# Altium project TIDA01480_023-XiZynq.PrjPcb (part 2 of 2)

## Sheet TIDA01480_pg4_DscrtRls.SchDoc
size 431 x 279 mm; Date: Not shown in title block; ApprovedBy: Not shown in title block; CheckedBy: Not shown in title block; Author: Not shown in title block; CompanyName: Not shown in title block; Engineer: Not shown in title block; Organization: Not shown in title block; Address1: Not shown in title block; Address2: Not shown in title block; Address3: Not shown in title block; Address4: Not shown in title block; DocumentNumber: 1; Revision: Use project parameter SCH_Rev; SheetNumber: 4; SheetTotal: 7; PageSetup: Record=PageOptions¦CenterHorizontal=True¦CenterVertical=True¦PrintScale=1.00¦XCorrection=1.00¦YCorrection=1.00¦PrintKind=0¦BorderSize=5000000¦LeftOffset=0¦BottomOffset=0¦Orientation=2¦PaperLength=1000¦PaperWidth=1000¦Scale=100¦PaperSource=15¦PrintQuality=600¦MediaType=1¦DitherType=10¦PaperKind=Letter¦PrintScaleMode=1
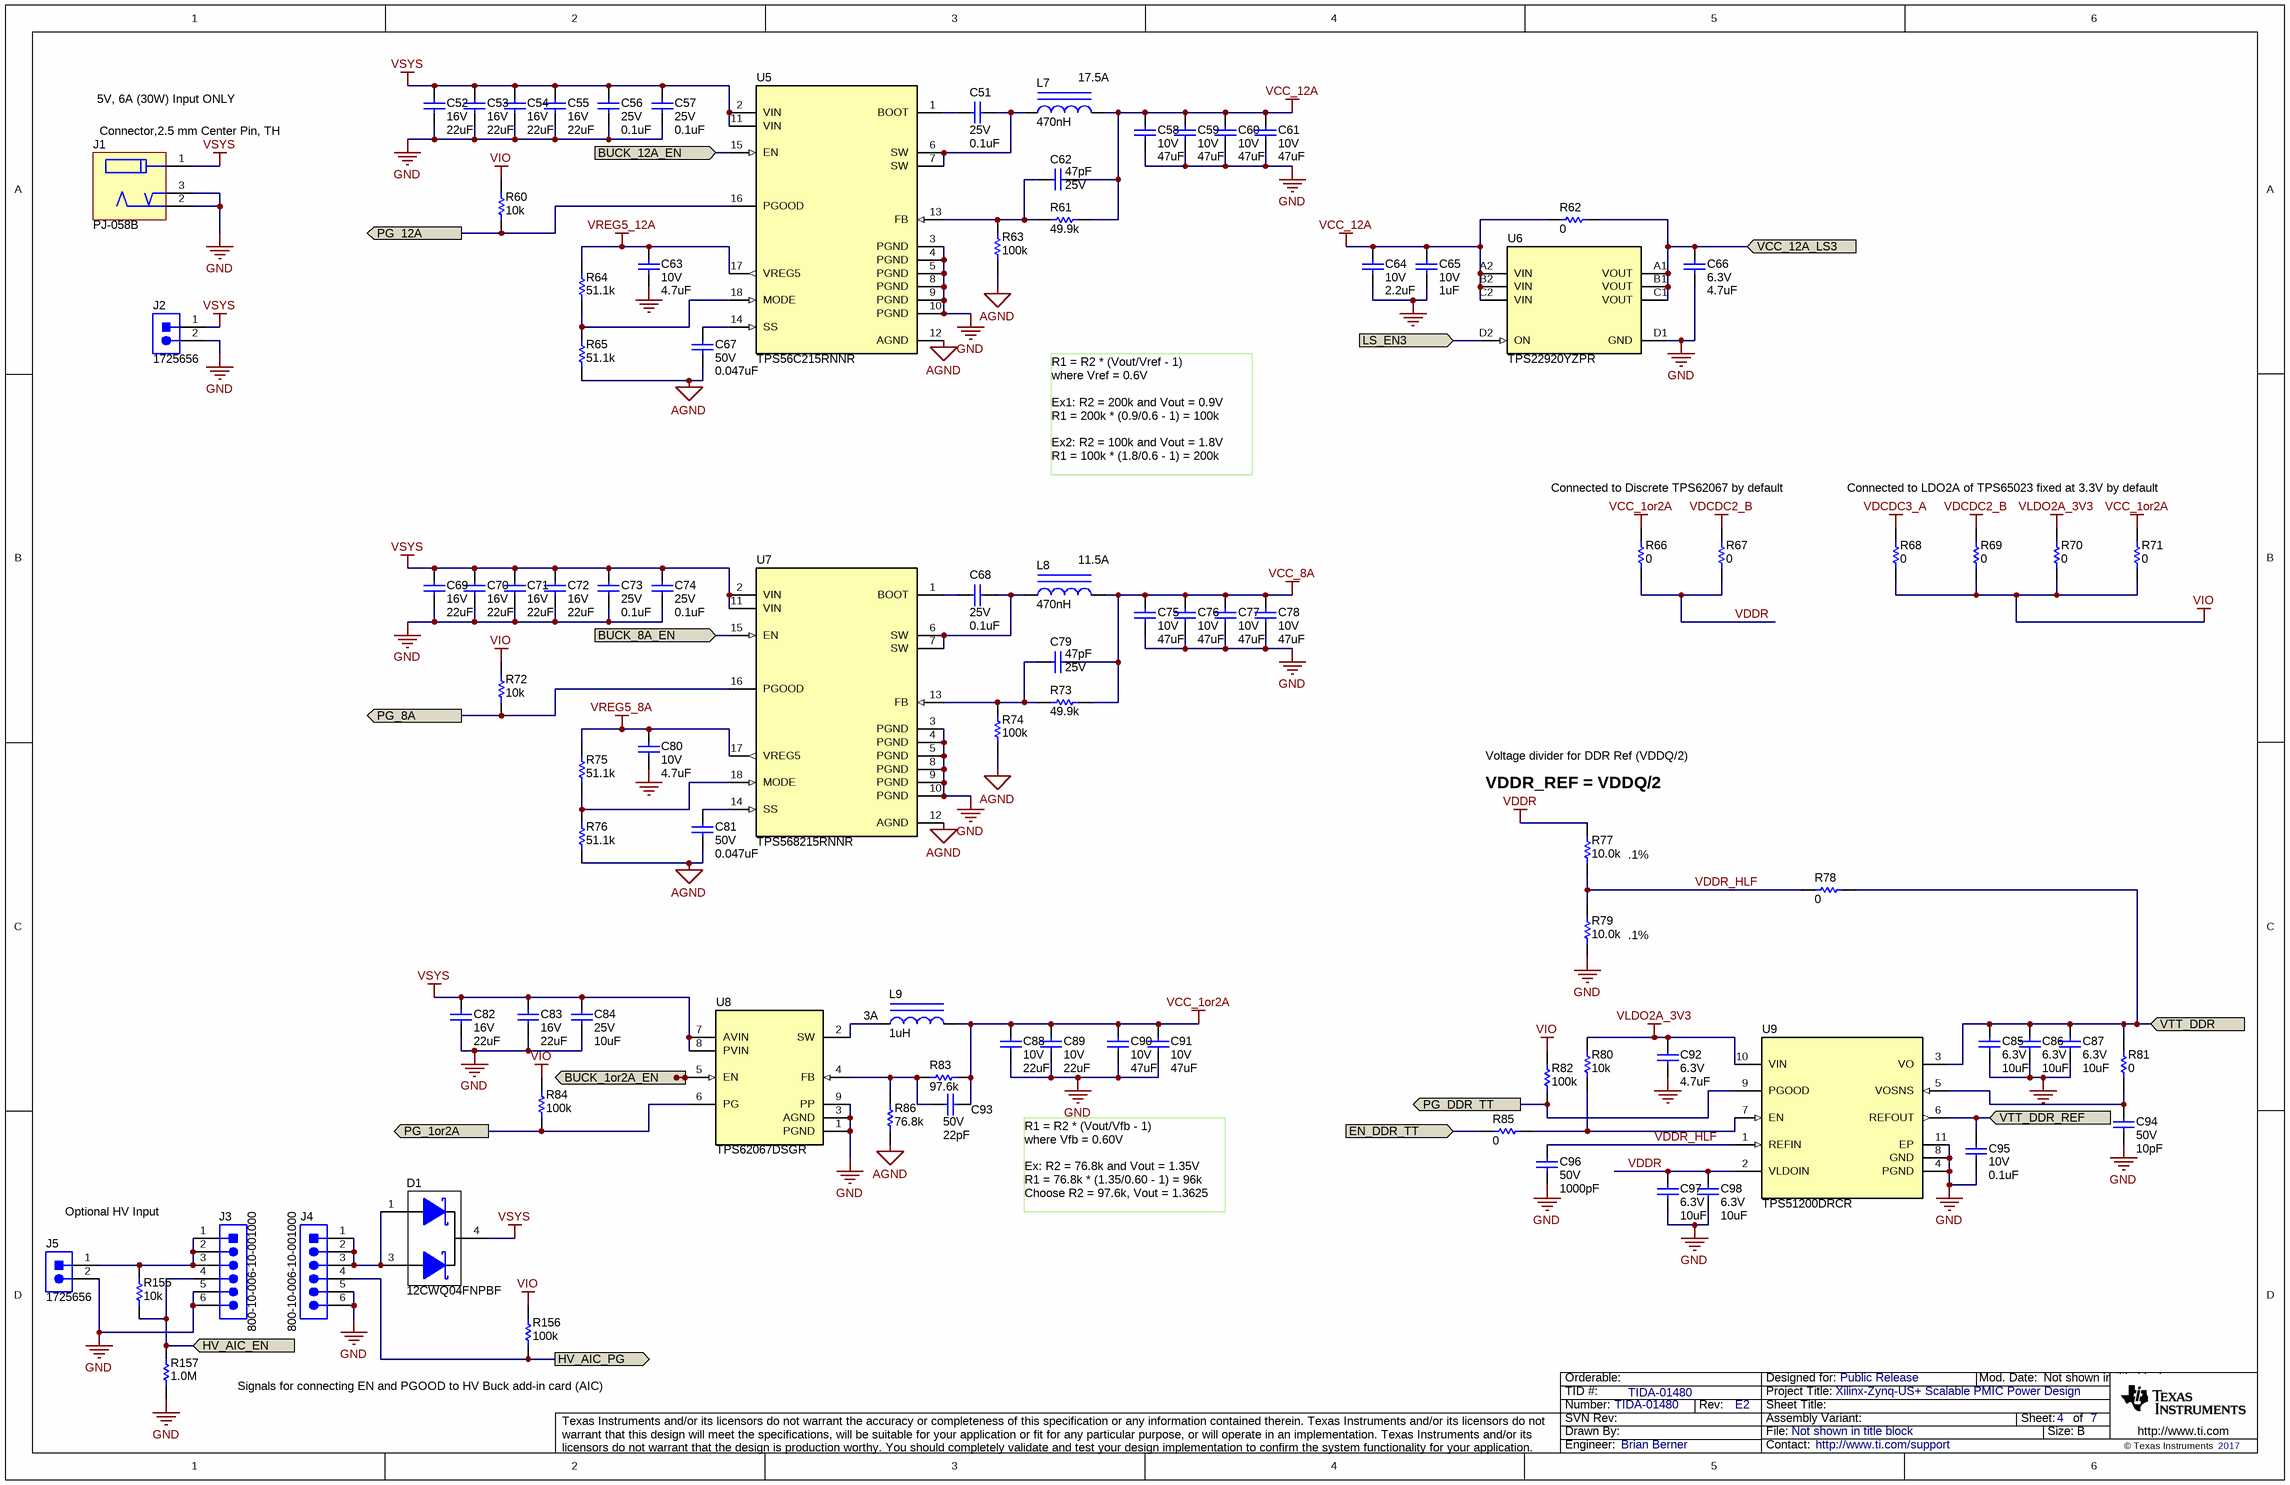
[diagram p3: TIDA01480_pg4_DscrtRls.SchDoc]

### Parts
C51  VDC_V: 25V  ValueDisplayed: 0.1uF  [0402]  (hidden comment: C1005X7R1E104M050BB)
C52  VDC_V: 16V  ValueDisplayed: 22uF  [1210_280]  (hidden comment: C3225X7R1C226K250AC)
C53  VDC_V: 16V  ValueDisplayed: 22uF  [1210_280]  (hidden comment: C3225X7R1C226K250AC)
C54  VDC_V: 16V  ValueDisplayed: 22uF  [1210_280]  (hidden comment: C3225X7R1C226K250AC)
C55  VDC_V: 16V  ValueDisplayed: 22uF  [1210_280]  (hidden comment: C3225X7R1C226K250AC)
C56  VDC_V: 25V  ValueDisplayed: 0.1uF  [0402]  (hidden comment: C1005X7R1E104M050BB)
C57  VDC_V: 25V  ValueDisplayed: 0.1uF  [0402]  (hidden comment: C1005X7R1E104M050BB)
C58  VDC_V: 10V  ValueDisplayed: 47uF  [1210_270]  (hidden comment: GRM32ER71A476KE15L)
C59  VDC_V: 10V  ValueDisplayed: 47uF  [1210_270]  (hidden comment: GRM32ER71A476KE15L)
C60  VDC_V: 10V  ValueDisplayed: 47uF  [1210_270]  (hidden comment: GRM32ER71A476KE15L)
C61  VDC_V: 10V  ValueDisplayed: 47uF  [1210_270]  (hidden comment: GRM32ER71A476KE15L)
C62  VDC_V: 25V  ValueDisplayed: 47pF  [0402]  (hidden comment: GRM1555C1E470JA01D)
C63  VDC_V: 10V  ValueDisplayed: 4.7uF  [0603]  (hidden comment: CGB3B1X5R1A475K055AC)
C64  VDC_V: 10V  ValueDisplayed: 2.2uF  [0603]  (hidden comment: GRM188R71A225KE15D)
C65  VDC_V: 10V  ValueDisplayed: 1uF  [0402]  (hidden comment: GRM155R61A105ME15D)
C66  VDC_V: 6.3V  ValueDisplayed: 4.7uF  [0603]  (hidden comment: JMK107BB7475MA-T)
C67  VDC_V: 50V  ValueDisplayed: 0.047uF  [0402]  (hidden comment: C1005X7R1H473K050BB)
C68  VDC_V: 25V  ValueDisplayed: 0.1uF  [0402]  (hidden comment: C1005X7R1E104M050BB)
C69  VDC_V: 16V  ValueDisplayed: 22uF  [1210_280]  (hidden comment: C3225X7R1C226K250AC)
C70  VDC_V: 16V  ValueDisplayed: 22uF  [1210_280]  (hidden comment: C3225X7R1C226K250AC)
C71  VDC_V: 16V  ValueDisplayed: 22uF  [1210_280]  (hidden comment: C3225X7R1C226K250AC)
C72  VDC_V: 16V  ValueDisplayed: 22uF  [1210_280]  (hidden comment: C3225X7R1C226K250AC)
C73  VDC_V: 25V  ValueDisplayed: 0.1uF  [0402]  (hidden comment: C1005X7R1E104M050BB)
C74  VDC_V: 25V  ValueDisplayed: 0.1uF  [0402]  (hidden comment: C1005X7R1E104M050BB)
C75  VDC_V: 10V  ValueDisplayed: 47uF  [1210_270]  (hidden comment: GRM32ER71A476KE15L)
C76  VDC_V: 10V  ValueDisplayed: 47uF  [1210_270]  (hidden comment: GRM32ER71A476KE15L)
C77  VDC_V: 10V  ValueDisplayed: 47uF  [1210_270]  (hidden comment: GRM32ER71A476KE15L)
C78  VDC_V: 10V  ValueDisplayed: 47uF  [1210_270]  (hidden comment: GRM32ER71A476KE15L)
C79  VDC_V: 25V  ValueDisplayed: 47pF  [0402]  (hidden comment: GRM1555C1E470JA01D)
C80  VDC_V: 10V  ValueDisplayed: 4.7uF  [0603]  (hidden comment: CGB3B1X5R1A475K055AC)
C81  VDC_V: 50V  ValueDisplayed: 0.047uF  [0402]  (hidden comment: C1005X7R1H473K050BB)
C82  VDC_V: 16V  ValueDisplayed: 22uF  [1210_280]  (hidden comment: C3225X7R1C226K250AC)
C83  VDC_V: 16V  ValueDisplayed: 22uF  [1210_280]  (hidden comment: C3225X7R1C226K250AC)
C84  VDC_V: 25V  ValueDisplayed: 10uF  [1206_190]  (hidden comment: C3216X7R1E106M160AE)
C85  VDC_V: 6.3V  ValueDisplayed: 10uF  [0805_HV]  (hidden comment: GRM21BR70J106KE76L)
C86  VDC_V: 6.3V  ValueDisplayed: 10uF  [0805_HV]  (hidden comment: GRM21BR70J106KE76L)
C87  VDC_V: 6.3V  ValueDisplayed: 10uF  [0805_HV]  (hidden comment: GRM21BR70J106KE76L)
C88  VDC_V: 10V  ValueDisplayed: 22uF  [0805_HV]  (hidden comment: C2012X7S1A226M125AC)
C89  VDC_V: 10V  ValueDisplayed: 22uF  [0805_HV]  (hidden comment: C2012X7S1A226M125AC)
C90  VDC_V: 10V  ValueDisplayed: 47uF  [1210_270]  (hidden comment: GRM32ER71A476KE15L)
C91  VDC_V: 10V  ValueDisplayed: 47uF  [1210_270]  (hidden comment: GRM32ER71A476KE15L)
C92  VDC_V: 6.3V  ValueDisplayed: 4.7uF  [0805_HV]  (hidden comment: GRM21BR60J475KA11L)
C93  VDC_V: 50V  ValueDisplayed: 22pF  [0402]  (hidden comment: GCM1555C1H220JA16D)
C94  VDC_V: 50V  ValueDisplayed: 10pF  [0402]  (hidden comment: GRM1555C1H100JA01D)
C95  VDC_V: 10V  ValueDisplayed: 0.1uF  [0402]  (hidden comment: GRM155R71A104KA01D)
C96  VDC_V: 50V  ValueDisplayed: 1000pF  [0402]  (hidden comment: C1005X7R1H102M050BE)
C97  VDC_V: 6.3V  ValueDisplayed: 10uF  [0805_HV]  (hidden comment: GRM21BR70J106KE76L)
C98  VDC_V: 6.3V  ValueDisplayed: 10uF  [0805_HV]  (hidden comment: GRM21BR70J106KE76L)
D1  12CWQ04FNPBF  [DPAK]
J1  PJ-058B  PackageReference: Connector,2.5 mm Center Pin, TH  [CUI_PJ-058B]
J2  1725656  [CONN_1725656]
J3  800-10-006-10-001000  [Mill-Max_800-10-006-10-001000]
J4  800-10-006-10-001000  [Mill-Max_800-10-006-10-001000]
J5  1725656  [CONN_1725656]
L7  Imax_A: 17.5A  ValueDisplayed: 470nH  [IHLP-2525CZ]  (hidden comment: IHLP2525CZERR47M01)
L8  Imax_A: 11.5A  ValueDisplayed: 470nH  [IHLP-2020BZ]  (hidden comment: IHLP2020BZERR47M01)
L9  Imax_A: 3A  ValueDisplayed: 1uH  [IHLP-1212AB]  (hidden comment: IHLP1212ABER1R0M11)
R60  ValueDisplayed: 10k  [0402]  (hidden comment: CRCW040210K0JNED)
R61  ValueDisplayed: 49.9k  [0402]  (hidden comment: ERJ-2RKF4992X)
R62  ValueDisplayed: 0  [1206]  (hidden comment: CRCW12060000Z0EA)
R63  ValueDisplayed: 100k  [0402]  (hidden comment: RG1005P-104-B-T5)
R64  ValueDisplayed: 51.1k  [0402]  (hidden comment: CRCW040251K1FKED)
R65  ValueDisplayed: 51.1k  [0402]  (hidden comment: CRCW040251K1FKED)
R66  ValueDisplayed: 0  [1206]  (hidden comment: CRCW12060000Z0EA)
R67  ValueDisplayed: 0  [1206]  (hidden comment: CRCW12060000Z0EA)
R68  ValueDisplayed: 0  [1206]  (hidden comment: CRCW12060000Z0EA)
R69  ValueDisplayed: 0  [1206]  (hidden comment: CRCW12060000Z0EA)
R70  ValueDisplayed: 0  [1206]  (hidden comment: CRCW12060000Z0EA)
R71  ValueDisplayed: 0  [1206]  (hidden comment: CRCW12060000Z0EA)
R72  ValueDisplayed: 10k  [0402]  (hidden comment: CRCW040210K0JNED)
R73  ValueDisplayed: 49.9k  [0402]  (hidden comment: ERJ-2RKF4992X)
R74  ValueDisplayed: 100k  [0402]  (hidden comment: RG1005P-104-B-T5)
R75  ValueDisplayed: 51.1k  [0402]  (hidden comment: CRCW040251K1FKED)
R76  ValueDisplayed: 51.1k  [0402]  (hidden comment: CRCW040251K1FKED)
R77  Value1: .1%  ValueDisplayed: 10.0k  [0402]  (hidden comment: RT0402BRD0710KL)
R78  ValueDisplayed: 0  [1206]  (hidden comment: CRCW12060000Z0EA)
R79  Value1: .1%  ValueDisplayed: 10.0k  [0402]  (hidden comment: RT0402BRD0710KL)
R80  ValueDisplayed: 10k  [0402]  (hidden comment: CRCW040210K0JNED)
R81  ValueDisplayed: 0  [0402]  (hidden comment: CRCW04020000Z0ED)
R82  ValueDisplayed: 100k  [0402]  (hidden comment: CRCW0402100KJNED)
R83  ValueDisplayed: 97.6k  [0402]  (hidden comment: ERJ-2RKF9762X)
R84  ValueDisplayed: 100k  [0402]  (hidden comment: CRCW0402100KJNED)
R85  ValueDisplayed: 0  [0402]  (hidden comment: CRCW04020000Z0ED)
R86  ValueDisplayed: 76.8k  [0402]  (hidden comment: ERA-2AEB7682X)
R155  ValueDisplayed: 10k  [0402]  (hidden comment: CRCW040210K0JNED)
R156  ValueDisplayed: 100k  [0402]  (hidden comment: CRCW0402100KJNED)
R157  ValueDisplayed: 1.0M  [0402]  (hidden comment: CRCW04021M00JNED)
U5  TPS56C215RNNR  [RNN0018A]
U6  TPS22920YZPR  [YZP0008ADCD]
U7  TPS568215RNNR  [RNN0018A]
U8  TPS62067DSGR  [DSG0008A]
U9  TPS51200DRCR  [DRC0010J]

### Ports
BUCK_1or2A_EN (in), BUCK_8A_EN (in), BUCK_12A_EN (in), EN_DDR_TT (in), HV_AIC_EN (in), HV_AIC_PG (out), LS_EN3 (in), PG_1or2A (out), PG_8A (out), PG_12A (out), PG_DDR_TT (out), VCC_12A_LS3, VTT_DDR, VTT_DDR_REF

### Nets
AGND: C67.2 C81.2 R63.1 R65.1 R74.1 R76.1 R86.1 U5.12(AGND) U7.12(AGND)
GND: C52.2 C53.2 C54.2 C55.2 C56.2 C57.2 C58.2 C59.2 C60.2 C61.2 C63.2 C64.2 C65.2 C66.2 C69.2 C70.2 C71.2 C72.2 C73.2 C74.2 C75.2 C76.2 C77.2 C78.2 C80.2 C82.2 C83.2 C84.2 C85.2 C86.2 C87.2 C88.2 C89.2 C90.2 C91.2 C92.2 C94.2 C95.2 C96.2 C97.2 C98.2 J1.2 J1.3 J2.2 J3.5 J3.6 J4.5 J4.6 J5.2 R79.1 R157.1 U5.3(PGND) U5.4(PGND) U5.5(PGND) U5.8(PGND) U5.9(PGND) U5.10(PGND) U6.D1(GND) U7.3(PGND) U7.4(PGND) U7.5(PGND) U7.8(PGND) U7.9(PGND) U7.10(PGND) U8.1(PGND) U8.3(AGND) U8.9(PP) U9.4(PGND) U9.8(GND) U9.11(EP)
VCC_1or2A: C88.1 C89.1 C90.1 C91.1 C93.1 L9.2 R66.2 R71.2 R83.1
VCC_8A: C75.1 C76.1 C77.1 C78.1 C79.1 L8.2 R73.2
VCC_12A: C58.1 C59.1 C60.1 C61.1 C62.1 C64.1 C65.1 L7.2 R61.2 R62.1 U6.A2(VIN) U6.B2(VIN) U6.C2(VIN)
VDCDC2_B: R67.2 R69.2
VDCDC3_A: R68.2
VDDR: C97.1 C98.1 R66.1 R67.1 R77.2 U9.2(VLDOIN)
VIO: R60.1 R68.1 R69.1 R70.1 R71.1 R72.1 R82.1 R84.1 R156.1
VLDO2A_3V3: C92.1 R70.2 R80.1 U9.10(VIN)
VREG5_8A: C80.1 R75.2 U7.17(VREG5)
VREG5_12A: C63.1 R64.2 U5.17(VREG5)
VSYS: C52.1 C53.1 C54.1 C55.1 C56.1 C57.1 C69.1 C70.1 C71.1 C72.1 C73.1 C74.1 C82.1 C83.1 C84.1 D1.4(K) J1.1 J2.1 U5.2(VIN) U5.11(VIN) U7.2(VIN) U7.11(VIN) U8.7(AVIN) U8.8(PVIN)
BUCK_1or2A_EN: U8.5(EN) ; port BUCK_1or2A_EN
BUCK_8A_EN: U7.15(EN) ; port BUCK_8A_EN
BUCK_12A_EN: U5.15(EN) ; port BUCK_12A_EN
DDR_Strt_PG: R84.2 U8.6(PG) ; port PG_1or2A
DDR_TT_PG: R82.2 U9.9(PGOOD) ; port PG_DDR_TT
EN_DDR_TERM: R85.2 ; port EN_DDR_TT
EN_PRE_BUCK: J3.4 R155.2 R157.2 ; port HV_AIC_EN
EN_SEQ_LS3: U6.D2(ON) ; port LS_EN3
HiCurrent_PG: R60.2 U5.16(PGOOD) ; port PG_12A
HV_AIC_PG: J4.4 R156.2 ; port HV_AIC_PG
MidCurrent_PG: R72.2 U7.16(PGOOD) ; port PG_8A
VCC_12A_LS3: C66.1 R62.2 U6.A1(VOUT) U6.B1(VOUT) U6.C1(VOUT) ; port VCC_12A_LS3
VDDR_HLF: C96.1 R77.1 R78.1 R79.2 U9.1(REFIN)
VREFCA_DDR: C95.1 U9.6(REFOUT) ; port VTT_DDR_REF
VTT: C85.1 C86.1 C87.1 R78.2 R81.2 U9.3(VO) ; port VTT_DDR
NetC51_1: C51.1 U5.1(BOOT)
NetC51_2: C51.2 L7.1 U5.6(SW) U5.7(SW)
NetC62_2: C62.2 R61.1 R63.2 U5.13(FB)
NetC67_1: C67.1 U5.14(SS)
NetC68_1: C68.1 U7.1(BOOT)
NetC68_2: C68.2 L8.1 U7.6(SW) U7.7(SW)
NetC79_2: C79.2 R73.1 R74.2 U7.13(FB)
NetC81_1: C81.1 U7.14(SS)
NetC93_2: C93.2 R83.2 R86.2 U8.4(FB)
NetC94_1: C94.1 R81.1 U9.5(VOSNS)
NetD1_1: D1.1(A) D1.3(A) J4.1 J4.2 J4.3
NetJ3_1: J3.1 J3.2 J3.3 J5.1 R155.1
NetL9_1: L9.1 U8.2(SW)
NetR64_1: R64.1 R65.2 U5.18(MODE)
NetR75_1: R75.1 R76.2 U7.18(MODE)
NetR80_2: R80.2 R85.1 U9.7(EN)

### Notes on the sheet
- 5V, 6A (30W) Input ONLY
- R1 = R2 * (Vout/Vref - 1)
  where Vref = 0.6V
  Ex1: R2 = 200k and Vout = 0.9V
  R1 = 200k * (0.9/0.6 - 1) = 100k
  Ex2: R2 = 100k and Vout = 1.8V
  R1 = 100k * (1.8/0.6 - 1) = 200k
- Connected to Discrete TPS62067 by default
- Connected to LDO2A of TPS65023 fixed at 3.3V by default
- Voltage divider for DDR Ref (VDDQ/2)
- (near R77) VDDR_REF = VDDQ/2
- Optional HV Input
- R1 = R2 * (Vout/Vfb - 1)
  where Vfb = 0.60V
  Ex: R2 = 76.8k and Vout = 1.35V
  R1 = 76.8k * (1.35/0.60 - 1) = 96k
  Choose R2 = 97.6k, Vout = 1.3625
- (near R156) Signals for connecting EN and PGOOD to HV Buck add-in card (AIC)

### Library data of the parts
C51 C56 C57 C68 C73 C74 = CMP-0006295-2: CAP, CERM, 0.1 uF, 25 V, +/- 20%, X7R, 0402; Manufacturer: TDK; TaMin_C: -55°C; Polarized: N; SizeAreaWB_mm2: 3; Value1: Unknown; U/M: EA; Value: 0.1uF; TaMax_C: 125°C; SizeZ_mm: 0.6; SizeX_mm: 1; SizeY_mm: 0.5; Cap_F: 100nF; AEC Category: Q200
C52-C55 C69-C72 C82 C83 = CMP-0009116-1: CAP, CERM, 22 uF, 16 V, +/- 10%, X7R, 1210; Manufacturer: TDK; TaMin_C: -55°C; ESR_ohm: 2.582m; Polarized: N; SizeAreaWB_mm2: 14.7; Value1: 0.002582 ohm; U/M: EA; Value: 22uF; TaMax_C: 125°C; SizeZ_mm: 2.8; SizeX_mm: 3.2; SizeY_mm: 2.5; SizeArea_mm2: 8; Cap_F: 22µF; IRMS_A: 4.57562A; AEC Category: Q200
C58-C61 C75-C78 C90 C91 = CMP-0009220-2: CAP, CERM, 47 uF, 10 V, +/- 10%, X7R, 1210; Manufacturer: MuRata; TaMin_C: -55°C; Polarized: N; SizeAreaWB_mm2: 14.7; Value1: Unknown; U/M: EA; Value: 47uF; TaMax_C: 125°C; SizeZ_mm: 2.7; SizeX_mm: 3.2; SizeY_mm: 2.5; Cap_Case: 1210; SizeArea_mm2: 8; Cap_F: 47µF; AEC Category: Q200
C62 C79 = CMP-0006388-2: CAP, CERM, 47 pF, 25 V, +/- 5%, C0G/NP0, 0402; Manufacturer: MuRata; TaMin_C: -55°C; Polarized: N; SizeAreaWB_mm2: 3; Value1: Unknown; U/M: EA; Value: 47pF; TaMax_C: 125°C; SizeZ_mm: 0.6; SizeX_mm: 1; SizeY_mm: 0.5; AEC Category: Q200
C63 C80 = CMP-0007105-5: CAP, CERM, 4.7 uF, 10 V, +/- 10%, X5R, 0603; Manufacturer: TDK; TaMin_C: -55°C; Polarized: N; SizeAreaWB_mm2: 4.68; Value1: Unknown; U/M: EA; Value: 4.7uF; TaMax_C: 85°C; SizeZ_mm: 1; SizeX_mm: 1.6; SizeY_mm: 0.8; SizeArea_mm2: 1.28; Cap_F: 4.7µF; AEC Category: Q200
C64 = CMP-0007370-3: CAP, CERM, 2.2 uF, 10 V, +/- 10%, X7R, 0603; Manufacturer: MuRata; TaMin_C: -55°C; ESR_ohm: 9m; Polarized: N; SizeAreaWB_mm2: 4.68; Value1: 0.009 ohm; U/M: EA; Value: 2.2uF; TaMax_C: 125°C; SizeZ_mm: 1; SizeX_mm: 1.6; SizeY_mm: 0.8; SizeArea_mm2: 1.28; Cap_F: 2.2µF; AEC Category: Q200
C65 = CMP-0064927-2: CAP, CERM, 1 uF, 10 V,+/- 20%, X5R, 0402; Manufacturer: MuRata; TaMin_C: -55°C; Polarized: N; SizeAreaWB_mm2: 3; Value1: Unknown; U/M: EA; Value: 1uF; TaMax_C: 85°C; SizeZ_mm: 0.6; SizeX_mm: 1; SizeY_mm: 0.5; CompType: Capacitor; Cap_F: 1µF; AEC Category: Q200
C66 = CMP-0007503-3: CAP, CERM, 4.7 uF, 6.3 V, +/- 10%, X7R, 0603; Manufacturer: Taiyo Yuden; TaMin_C: -55°C; Polarized: N; SizeAreaWB_mm2: 4.68; Value1: Unknown; U/M: EA; Value: 4.7uF; TaMax_C: 125°C; SizeZ_mm: 1; SizeX_mm: 1.6; SizeY_mm: 0.8; SizeArea_mm2: 1.28; Cap_F: 4.7µF; AEC Category: Q200
C67 C81 = CMP-0006298-2: CAP, CERM, 0.047 uF, 50 V, +/- 10%, X7R, 0402; Manufacturer: TDK; TaMin_C: -55°C; ESR_ohm: 0.06407; Polarized: N; SizeAreaWB_mm2: 3; Value1: 0.06407 ohm; U/M: EA; SizeZ_mm: 0.6; SizeX_mm: 1; SizeY_mm: 0.5; Cap_F: 47nF; IRMS_A: 6.46122dA; AEC Category: Q200; TaMax_C: 125°C
C84 = CMP-0008692-2: CAP, CERM, 10 uF, 25 V, +/- 20%, X7R, 1206_190; Manufacturer: TDK; TaMin_C: -55°C; Polarized: N; SizeAreaWB_mm2: 10.92; Value1: Unknown; U/M: EA; Value: 10uF; TaMax_C: 125°C; SizeZ_mm: 1.9; SizeX_mm: 3.2; SizeY_mm: 1.6; Cap_Case: 1206; SizeArea_mm2: 5.12; CompType: Capacitor; Cap_F: 10µF; AEC Category: Q200
C85-C87 C97 C98 = CMP-0008311-2: CAP, CERM, 10 uF, 6.3 V, +/- 10%, X7R, 0805; Manufacturer: MuRata; TaMin_C: -55°C; Polarized: N; SizeAreaWB_mm2: 6.75; Value1: Unknown; U/M: EA; Value: 10uF; TaMax_C: 125°C; SizeZ_mm: 1.45; SizeX_mm: 2; SizeY_mm: 1.25; Cap_Case: 0805; SizeArea_mm2: 2.5; Cap_F: 10µF; AEC Category: Q200
C88 C89 = CMP-0007890-2: CAP, CERM, 22 uF, 10 V, +/- 20%, X7S, 0805; Manufacturer: TDK; TaMin_C: -55°C; ESR_ohm: 2.05m; Polarized: N; SizeAreaWB_mm2: 6.75; Value1: 0.00205 ohm; U/M: EA; Value: 22uF; TaMax_C: 125°C; SizeZ_mm: 1.45; SizeX_mm: 2; SizeY_mm: 1.25; Cap_Case: 0805; SizeArea_mm2: 2.5; Cap_F: 22µF; IRMS_A: 4.55587A; AEC Category: Q200
C92 = CMP-0008283-2: CAP, CERM, 4.7 uF, 6.3 V, +/- 10%, X5R, 0805; Manufacturer: MuRata; TaMin_C: -55°C; Polarized: N; SizeAreaWB_mm2: 6.75; Value1: Unknown; U/M: EA; Value: 4.7uF; TaMax_C: 85°C; SizeZ_mm: 1.45; SizeX_mm: 2; SizeY_mm: 1.25; Cap_Case: 0805; SizeArea_mm2: 2.5; Cap_F: 4.7µF; AEC Category: Q200
C93 = CMP-0006348-2: CAP, CERM, 22 pF, 50 V, +/- 5%, C0G/NP0, AEC-Q200 Grade 1, 0402; Manufacturer: MuRata; TaMin_C: -55°C; Polarized: N; SizeAreaWB_mm2: 3; Value1: Unknown; U/M: EA; Value: 22pF; TaMax_C: 125°C; SizeZ_mm: 0.6; SizeX_mm: 1; SizeY_mm: 0.5; AEC Qualified: Y; AEC Category: Q200
C94 = CMP-0006408-2: CAP, CERM, 10 pF, 50 V, +/- 5%, C0G/NP0, 0402; Manufacturer: MuRata; TaMin_C: -55°C; Polarized: N; SizeAreaWB_mm2: 3; Value1: Unknown; U/M: EA; Value: 10pF; TaMax_C: 125°C; SizeZ_mm: 0.6; SizeX_mm: 1; SizeY_mm: 0.5; AEC Category: Q200
C95 = CMP-0006629-2: CAP, CERM, 0.1 uF, 10 V, +/- 10%, X7R, 0402; Manufacturer: MuRata; TaMin_C: -55°C; Polarized: N; SizeAreaWB_mm2: 3; Value1: Unknown; U/M: EA; Value: 0.1uF; TaMax_C: 125°C; SizeZ_mm: 0.6; SizeX_mm: 1; SizeY_mm: 0.5; Cap_F: 100nF; AEC Category: Q200
C96 = CMP-0006296-2: CAP, CERM, 1000 pF, 50 V, +/- 20%, X7R, 0402; Manufacturer: TDK; TaMin_C: -55°C; Polarized: N; SizeAreaWB_mm2: 3; Value1: Unknown; U/M: EA; Value: 1000pF; TaMax_C: 125°C; SizeZ_mm: 0.6; SizeX_mm: 1; SizeY_mm: 0.5; Cap_F: 1nF; AEC Category: Q200
D1 = CMP-0028356-1: Diode, Schottky, 40 V, 12 A, DPAK; Manufacturer: Vishay-Semiconductor; Io_A: 12A; Green_Lifecycle: Not Set; SizeAreaWB_mm2: 101.7114; Vr_V: 40V; Green_REACh: Incomplete; TJmax_C: 150°C; U/M: EA; Value: 40V; SizeZ_mm: 2.29; SizeX_mm: 9.91; SizeY_mm: 6.54; Vf_V: 6.8dV; Value2: 0.68V; SizeArea_mm2: 64.8114; AEC Category: Q101; RJC_CperW: 1.5
J1 = CMP-0075310-1: Connector, DC Jack 2.5 mm Center Pin, TH; Manufacturer: CUI Inc.; CNHeader: False; Current_A: 2.5A; Gender: Female; Voltage_V: 24V; CompType: Power Jack; ContactFinish: Nickel; Cert_UL: Y
J2 J5 = CMP-0055479-1: Terminal Block, 100mil, 2x1, 6A, 63V, TH; Manufacturer: Phoenix Contact; CNHeader: FALSE; Green_Lifecycle: Not Set; Green_REACh: Incomplete; CT: TRUE
J3 J4 = CMP-0055084-1: Header, 100mil, 6x1, TH; Manufacturer: Mill-Max; CT: FALSE; CNHeader: TRUE
L7 = CMP-0063396-1: Inductor, Shielded Drum Core, Powdered Iron, 470 nH, 17.5 A, 0.004 ohm, SMD; Manufacturer: Vishay-Dale; Isat: 26A @ 20% inductance drop; Irms: 17.5A @ 40C rise; Green_Lifecycle: Active; SizeAreaWB_mm2: 75.0442; DCR_ohm: 4m; Green_REACh: Passed; Value: 470nH; SizeZ_mm: 3; SizeX_mm: 6.86; SizeY_mm: 6.47; SizeArea_mm2: 44.3842; AEC Category: Q200
L8 = CMP-0063307-1: Inductor, Shielded Drum Core, Powdered Iron, 470 nH, 11.5 A, 0.0081 ohm, SMD; Manufacturer: Vishay-Dale; Isat: 21A @ 20% inductance drop; Irms: 11.5A @ 40C rise; Green_Lifecycle: Active; SizeAreaWB_mm2: 53.7782; DCR_ohm: 8.1m; Green_REACh: Passed; Value: 470nH; SizeZ_mm: 2; SizeX_mm: 5.49; SizeY_mm: 5.18; SizeArea_mm2: 28.4382; AEC Category: Q200
L9 = CMP-0063238-1: Inductor, Shielded Drum Core, Powdered Iron, 1 uH, 3 A, 0.038 ohm, SMD; Manufacturer: Vishay-Dale; Isat: 4.5A @ 20% inductance drop; Irms: 3A @ 40C rise; Green_Lifecycle: Active; SizeAreaWB_mm2: 19.32; DCR_ohm: 0.038; Green_REACh: Passed; Value: 1uH; SizeZ_mm: 1.2; SizeX_mm: 3.6; SizeY_mm: 3.2; SizeArea_mm2: 11.52; Ind_H: 1µH; AEC Category: Q200
R60 R72 R80 R155 = CMP-0026825-4: RES, 10 k, 5%, 0.063 W, 0402; Manufacturer: Vishay-Dale; Power_W: 63mW; TempCo: 200 ppm/C; Value_Code: 10k0; U/M: EA; Value: 10k; EIA_Code: E24; SizeX_mm: 1; SizeY_mm: 0.5; SizeZ_mm: 0.6; Value2: 0.063W; VDC_V: 50V; AEC Category: Q200
R61 R73 = CMP-0026702-1: RES, 49.9 k, 1%, 0.1 W, AEC-Q200 Grade 0, 0402; Manufacturer: Panasonic; Power_W: 100mW; TempCo: 100 ppm/C; Value_Code: 49k9; U/M: EA; Value: 49.9k; EIA_Code: E96; SizeX_mm: 1; SizeY_mm: 0.5; SizeZ_mm: 0.6; Value2: 0.1W; AEC Qualified: Y; VDC_V: 50V; AEC Grade: 0; AEC Category: Q200
R62 R66-R71 R78 = CMP-0018573-2: RES, 0, 5%, 0.25 W, 1206; Manufacturer: Vishay-Dale; Power_W: 250mW; TempCo: 200 ppm/C; Value_Code: 0000; U/M: EA; Value: 0; EIA_Code: E24; SizeX_mm: 3.2; SizeY_mm: 1.6; SizeZ_mm: 1.35; Value2: 0.25W; SizeArea_mm2: 5.12; VDC_V: 200V; AEC Category: Q200
R63 R74 = CMP-0026815-1: RES, 100 k, 0.1%, 0.063 W, 0402; Manufacturer: Susumu Co Ltd; Power_W: 63mW; TempCo: 25 ppm/C; U/M: EA; Value: 100k; EIA_Code: E192; SizeX_mm: 1; SizeY_mm: 0.5; SizeZ_mm: 0.6; Value2: 0.063W; AEC Category: Q200
R64 R65 R75 R76 = CMP-0026437-1: RES, 51.1 k, 1%, 0.063 W, 0402; Manufacturer: Vishay-Dale; Power_W: 63mW; TempCo: 100 ppm/C; Value_Code: 51k1; U/M: EA; Value: 51.1k; EIA_Code: E96; SizeX_mm: 1; SizeY_mm: 0.5; SizeZ_mm: 0.6; Value2: 0.063W; VDC_V: 50V; AEC Category: Q200
R77 R79 = CMP-0065360-1: RES, 10.0 k, .1%, .0625 W, 0402; Manufacturer: Yageo America; Power_W: 62.5mW; TempCo: 25 ppm/C; Value_Code: 10k0; U/M: EA; Value: 10.0k; EIA_Code: E192; Tolerance_%: 0.1%; Res_ohm: 10k; SizeX_mm: 1.0; SizeY_mm: 0.5; SizeZ_mm: 0.6; Value2: .0625W; CompType: Resistor; VDC_V: 50V; AEC Category: Q200
R81 R85 = CMP-0026822-2: RES, 0, 5%, 0.063 W, 0402; Manufacturer: Vishay-Dale; Power_W: 63mW; TempCo: 200 ppm/C; Value_Code: 0000; U/M: EA; Value: 0; EIA_Code: E24; SizeX_mm: 1; SizeY_mm: 0.5; SizeZ_mm: 0.6; Value2: 0.063W; VDC_V: 50V; AEC Category: Q200
R82 R84 R156 = CMP-0026823-2: RES, 100 k, 5%, 0.063 W, 0402; Manufacturer: Vishay-Dale; Power_W: 63mW; TempCo: 200 ppm/C; U/M: EA; Value: 100k; EIA_Code: E24; SizeX_mm: 1; SizeY_mm: 0.5; SizeZ_mm: 0.6; Value2: 0.063W; VDC_V: 50V; AEC Category: Q200
R83 = CMP-0026712-1: RES, 97.6 k, 1%, 0.1 W, AEC-Q200 Grade 0, 0402; Manufacturer: Panasonic; Power_W: 100mW; TempCo: 100 ppm/C; Value_Code: 97k6; U/M: EA; Value: 97.6k; EIA_Code: E96; SizeX_mm: 1; SizeY_mm: 0.5; SizeZ_mm: 0.6; Value2: 0.1W; AEC Qualified: Y; VDC_V: 50V; AEC Grade: 0; AEC Category: Q200
R86 = CMP-0026787-1: RES, 76.8 k, 0.1%, 0.063 W, AEC-Q200 Grade 0, 0402; Manufacturer: Panasonic; Power_W: 63mW; TempCo: 25 ppm/C; Value_Code: 76k8; U/M: EA; Value: 76.8k; EIA_Code: E192; SizeX_mm: 1; SizeY_mm: 0.5; SizeZ_mm: 0.6; Value2: 0.063W; AEC Qualified: Y; VDC_V: 50V; AEC Grade: 0; AEC Category: Q200
R157 = CMP-0026859-1: RES, 1.0 M, 5%, 0.063 W, 0402; Manufacturer: Vishay-Dale; Power_W: 63mW; TempCo: 200 ppm/C; Value_Code: 1M00; U/M: EA; Value: 1.0Meg; EIA_Code: E24; Res_ohm: 1M; SizeX_mm: 1; SizeY_mm: 0.5; SizeZ_mm: 0.6; Value2: 0.063W; VDC_V: 50V; AEC Category: Q200
U5 = CMP-0074013-1: 4.5V to 17V Input, DCAP3 Mode, 12A Synchronous Step-Down SWIFT(TM) Converter, RNN0018A (VQFN-HR-18); Alternate PartNumber: TPS56C215RNNT; Alternate Manufacturer: Texas Instruments; SizeAreaWB_mm2: 20.25; U/M: EA; SizeZ_mm: 1.0; SizeX_mm: 3.5; SizeArea_mm2: 12.25; CompType: IC
U6 = CMP-0066647-2: 3.6V, 4A, 5.3mΩ Load Switch with Quick Output Discharge, YZP0008ADCD (DSBGA-8); Alternate PartNumber: TPS22920YZPT; Alternate Manufacturer: Texas Instruments; Green_Lifecycle: Active; SizeAreaWB_mm2: 7.3125; Green_REACh: Passed; U/M: EA; SizeZ_mm: 0.5; SizeX_mm: 1.25; SizeY_mm: 2.25; SizeArea_mm2: 2.8125; CompType: IC
U7 = CMP-0074010-1: 4.5V to 17V Input, DCAP3 Mode, 8A Synchronous SWIFT(TM) Step-Down Converter, RNN0018A (VQFN-HR-18); Alternate PartNumber: TPS568215RNNT; Alternate Manufacturer: Texas Instruments; SizeAreaWB_mm2: 20.25; U/M: EA; SizeZ_mm: 1.0; SizeX_mm: 3.5; SizeArea_mm2: 12.25; CompType: IC
U8 = CMP-0037738-2: Buck Step Down Regulator with 2.9 to 6 V Input and 0.8 to 6 V Output, -40 to 85 degC, 8-Pin WSON (DSG), Green (RoHS & no Sb/Br); Manufacturer: Texas Instruments; Vin(Min)(V): 2.9; Switch Current Limit(Typ)(A): 2.75; Vin(Max)(V): 6; Rating: Catalog; Vout(Min)(V): 0.8; Duty Cycle(Max)(%): 100; Regulated Outputs(#): 1; SubFamily: Step-Down Regulator; Synchronous Rectification: TRUE; Iq(Typ)(mA): 0.018; Iout(Max)(A): 2
U9 = CMP-0036438-2: Single Output LDO, 3 A, 2.375 to 3.5 V Input, with DDR Termination, 10-pin SON (DRC), -40 to 85 degC, Green (RoHS & no Sb/Br); Manufacturer: Texas Instruments; Vin(Min)(V): 2.3; Power Good: TRUE; Vin(Max)(V): 3.5; Rating: Catalog; SubFamily: Single Channel LDO; Iq(Typ)(mA): 0.5; Iout(Max)(A): 3

## Sheet TIDA01480_pg7_Hardware.SchDoc
size 431 x 279 mm; Date: Not shown in title block; ApprovedBy: Not shown in title block; CheckedBy: Not shown in title block; Author: Not shown in title block; CompanyName: Not shown in title block; Engineer: Not shown in title block; Organization: Not shown in title block; Address1: Not shown in title block; Address2: Not shown in title block; Address3: Not shown in title block; Address4: Not shown in title block; DocumentNumber: 1; Revision: Use project parameter SCH_Rev; SheetNumber: 7; SheetTotal: 7; PageSetup: Record=PageOptions¦CenterHorizontal=True¦CenterVertical=True¦PrintScale=1.00¦XCorrection=1.00¦YCorrection=1.00¦PrintKind=0¦BorderSize=5000000¦LeftOffset=0¦BottomOffset=0¦Orientation=2¦PaperLength=1000¦PaperWidth=1000¦Scale=100¦PaperSource=15¦PrintQuality=600¦MediaType=1¦DitherType=10¦PaperKind=Letter¦PrintScaleMode=1
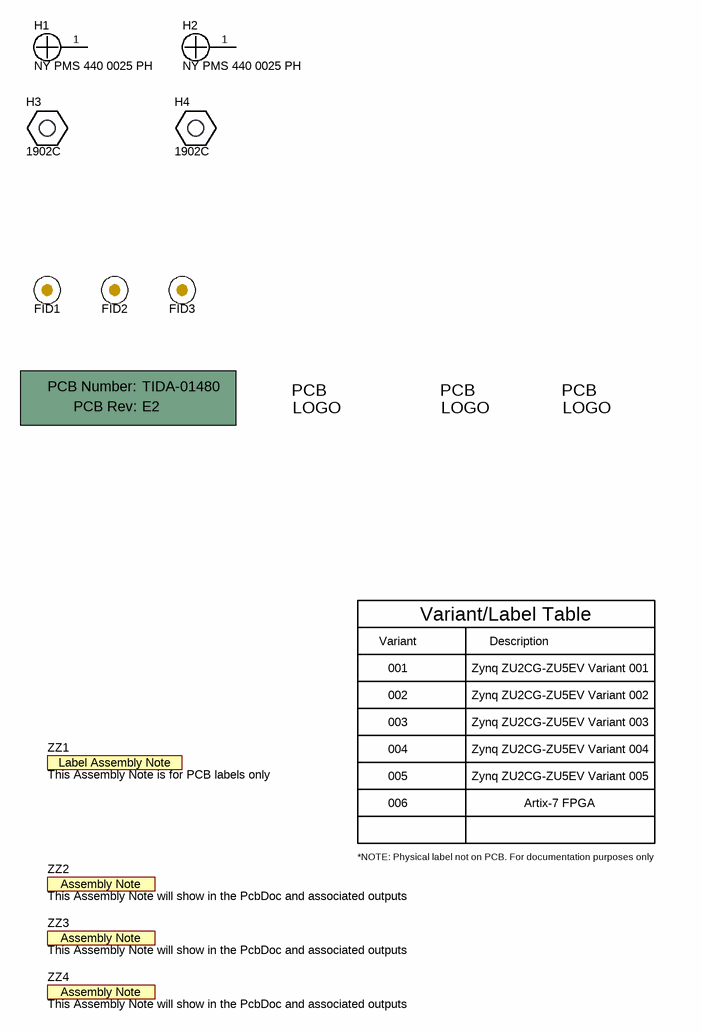
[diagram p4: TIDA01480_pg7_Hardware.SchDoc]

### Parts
!PCB  Printed Circuit Board  (value not drawn)  (mechanical)
FID1  Fiducial  [Fiducial10-20]  (value not drawn)
FID2  Fiducial  [Fiducial10-20]  (value not drawn)
FID3  Fiducial  [Fiducial10-20]  (value not drawn)
H1  NY PMS 440 0025 PH  [NY PMS 440 0025 PH]
H2  NY PMS 440 0025 PH  [NY PMS 440 0025 PH]
H3  1902C  [Keystone_1902C]
H4  1902C  [Keystone_1902C]
Logo1  Texas Instruments  [TI_Stacked_Overlay_Small]  (value not drawn)  (no BOM)
Logo2  Pb-Free Symbol  [Pb-Free_Overlay_Small]  (value not drawn)  (no BOM)
Logo3  FCC disclaimer  [FCC_disclaimer]  (value not drawn)  (no BOM)
ZZ1  This Assembly Note is for PCB labels only  [AssemblyNoteLabel]  (no BOM)
ZZ2  This Assembly Note will show in the PcbDoc and associated outputs  [AssemblyNote]  (no BOM)
ZZ3  This Assembly Note will show in the PcbDoc and associated outputs  [AssemblyNote]  (no BOM)
ZZ4  This Assembly Note will show in the PcbDoc and associated outputs  [AssemblyNote]  (no BOM)

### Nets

Not connected (* = marked no-connect by the designer): H1 1; H2 1

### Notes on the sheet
- Variant
- Variant/Label Table
- Description
- 001
- 002
- Zynq ZU2CG-ZU5EV Variant 001
- Zynq ZU2CG-ZU5EV Variant 002
- 003
- 004
- 005
- Zynq ZU2CG-ZU5EV Variant 003
- Zynq ZU2CG-ZU5EV Variant 004
- Zynq ZU2CG-ZU5EV Variant 005
- 006
- Artix-7 FPGA
- *NOTE: Physical label not on PCB. For documentation purposes only

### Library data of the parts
!PCB = PCB: Manufacturer: Any; PartNumber: TIDA-01480; SymbolCreator: a0412235
FID1-FID3 = Fiducial: Fiducial mark.  There is nothing to buy or mount.; SymbolCreator: codlsc
H1 H2 = NY PMS 440 0025 PH: Machine Screw, Round, #4-40 x 1/4, Nylon, Philips panhead; Manufacturer: B&F Fastener Supply; CompType: Hardware; SymbolCreator: codlsc; U/M: EA; Green_Lifecycle: Not Set; Green_REACh: Incomplete
H3 H4 = 1902C: Standoff, Hex, 0.5"L #4-40 Nylon; Manufacturer: Keystone; Green_Lifecycle: Active; Green_REACh: Passed; SymbolCreator: a0412235
Logo1 = TI_Logo: Texas Instrument Corporate Signature; SymbolCreator: a0412235
Logo2 = Pb-Free: SymbolCreator: a0412235
Logo3 = FCC_disclaimer: SymbolCreator: a0412235
ZZ1 = AssemblyNoteLabel: SymbolCreator: a0412235
ZZ2-ZZ4 = AssemblyNote: SymbolCreator: codlsc

## Sheet TIDA01480_pg1_Cover.SchDoc
size 431 x 279 mm; Date: Not shown in title block; ApprovedBy: Not shown in title block; CheckedBy: Not shown in title block; Author: Not shown in title block; CompanyName: Not shown in title block; Engineer: Not shown in title block; Organization: Not shown in title block; Address1: Not shown in title block; Address2: Not shown in title block; Address3: Not shown in title block; Address4: Not shown in title block; DocumentNumber: 1; Revision: Use project parameter SCH_Rev; SheetNumber: 1; SheetTotal: 7; PageSetup: Record=PageOptions¦CenterHorizontal=True¦CenterVertical=True¦PrintScale=1.00¦XCorrection=1.00¦YCorrection=1.00¦PrintKind=0¦BorderSize=5000000¦LeftOffset=0¦BottomOffset=0¦Orientation=2¦PaperLength=1000¦PaperWidth=1000¦Scale=100¦PaperSource=15¦PrintQuality=600¦MediaType=1¦DitherType=10¦PaperKind=Letter¦PrintScaleMode=1
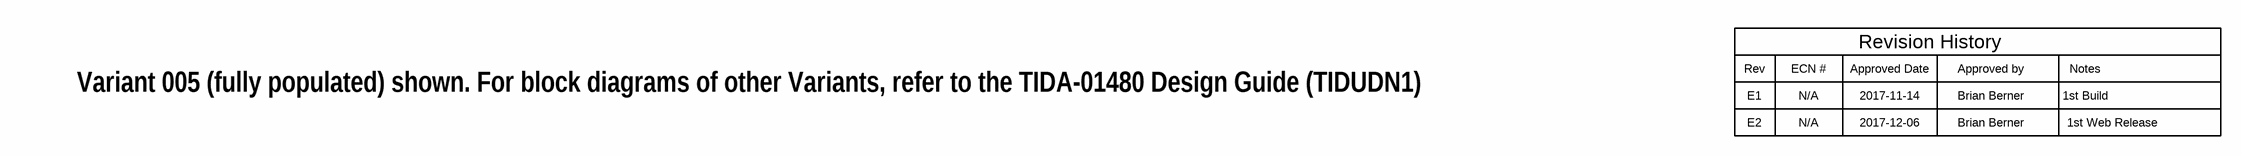
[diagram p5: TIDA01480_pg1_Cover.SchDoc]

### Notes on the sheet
- Variant 005 (fully populated) shown. For block diagrams of other Variants, refer to the TIDA-01480 Design Guide (TIDUDN1)
- Rev
- E1
- ECN #
- N/A
- Approved Date
- 2017-11-14
- Revision History
- Approved by
- Brian Berner
- Notes
- 1st Build
- E2
- 2017-12-06
- 1st Web Release

## Sheet TIDA01480_pg6_MiscSignals.SchDoc
size 431 x 279 mm; Date: Not shown in title block; ApprovedBy: Not shown in title block; CheckedBy: Not shown in title block; Author: Not shown in title block; CompanyName: Not shown in title block; Engineer: Not shown in title block; Organization: Not shown in title block; Address1: Not shown in title block; Address2: Not shown in title block; Address3: Not shown in title block; Address4: Not shown in title block; DocumentNumber: 1; Revision: Use project parameter SCH_Rev; SheetNumber: 6; SheetTotal: 7; PageSetup: Record=PageOptions¦CenterHorizontal=True¦CenterVertical=True¦PrintScale=1.00¦XCorrection=1.00¦YCorrection=1.00¦PrintKind=0¦BorderSize=5000000¦LeftOffset=0¦BottomOffset=0¦Orientation=2¦PaperLength=1000¦PaperWidth=1000¦Scale=100¦PaperSource=15¦PrintQuality=600¦MediaType=1¦DitherType=10¦PaperKind=Letter¦PrintScaleMode=1
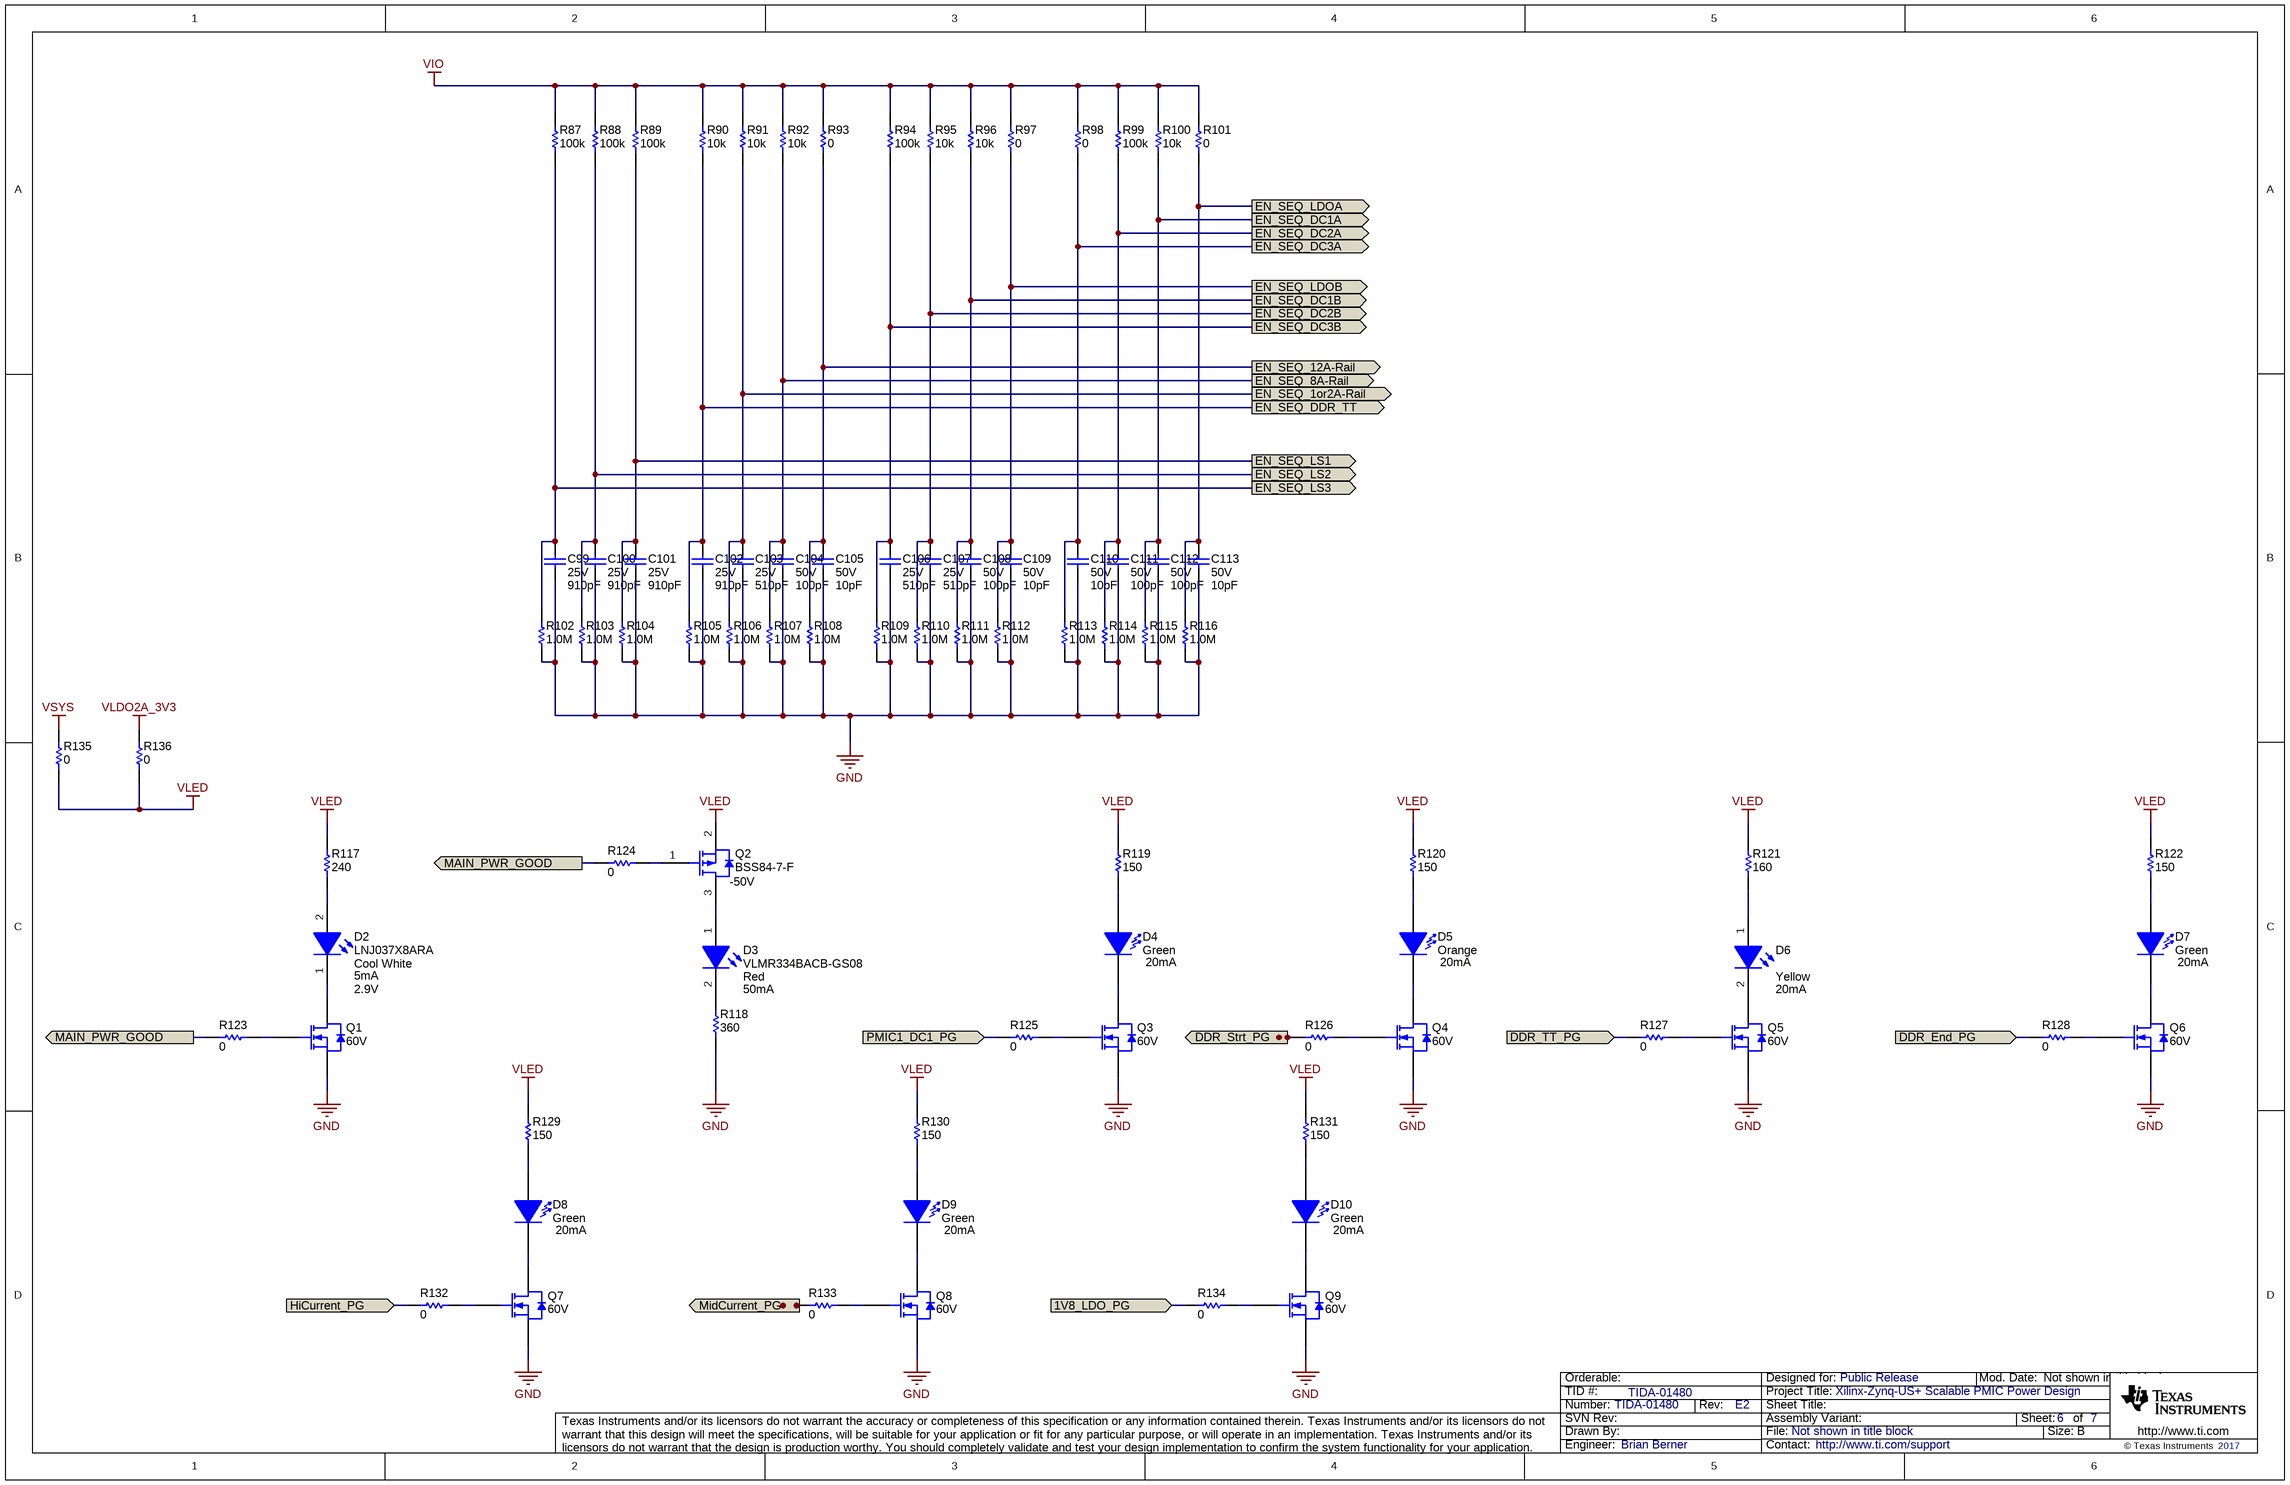
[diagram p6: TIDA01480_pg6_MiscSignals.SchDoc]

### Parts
C99  VDC_V: 25V  ValueDisplayed: 910pF  [0402]  (hidden comment: GRM1555C1E911JA01D)
C100  VDC_V: 25V  ValueDisplayed: 910pF  [0402]  (hidden comment: GRM1555C1E911JA01D)
C101  VDC_V: 25V  ValueDisplayed: 910pF  [0402]  (hidden comment: GRM1555C1E911JA01D)
C102  VDC_V: 25V  ValueDisplayed: 910pF  [0402]  (hidden comment: GRM1555C1E911JA01D)
C103  VDC_V: 25V  ValueDisplayed: 510pF  [0402]  (hidden comment: GRM1555C1E511JA01D)
C104  VDC_V: 50V  ValueDisplayed: 100pF  [0402]  (hidden comment: GRM1555C1H101JA01D)
C105  VDC_V: 50V  ValueDisplayed: 10pF  [0402]  (hidden comment: GRM1555C1H100FA01D)
C106  VDC_V: 25V  ValueDisplayed: 510pF  [0402]  (hidden comment: GRM1555C1E511JA01D)
C107  VDC_V: 25V  ValueDisplayed: 510pF  [0402]  (hidden comment: GRM1555C1E511JA01D)
C108  VDC_V: 50V  ValueDisplayed: 100pF  [0402]  (hidden comment: GRM1555C1H101JA01D)
C109  VDC_V: 50V  ValueDisplayed: 10pF  [0402]  (hidden comment: GRM1555C1H100FA01D)
C110  VDC_V: 50V  ValueDisplayed: 10pF  [0402]  (hidden comment: GRM1555C1H100FA01D)
C111  VDC_V: 50V  ValueDisplayed: 100pF  [0402]  (hidden comment: GRM1555C1H101JA01D)
C112  VDC_V: 50V  ValueDisplayed: 100pF  [0402]  (hidden comment: GRM1555C1H101JA01D)
C113  VDC_V: 50V  ValueDisplayed: 10pF  [0402]  (hidden comment: GRM1555C1H100FA01D)
D2  LNJ037X8ARA  value Cool White  Io_A: 5mA  Vf_V: 2.9V  [LNJ037X8_WHITE]
D3  VLMR334BACB-GS08  value Red  Io_A: 50mA  [VLMR334_Red]
D4  value Green  Io_A: 20mA  [LED_LTST-C190_G]  (hidden comment: LTST-C190KGKT)
D5  value Orange  Io_A: 20mA  [LED_LTST-C190]  (hidden comment: LTST-C190KFKT)
D6  value Yellow  Io_A: 20mA  [LED_LTST-C170]  (hidden comment: LTST-C170KSKT)
D7  value Green  Io_A: 20mA  [LED_LTST-C190_G]  (hidden comment: LTST-C190KGKT)
D8  value Green  Io_A: 20mA  [LED_LTST-C190_G]  (hidden comment: LTST-C190KGKT)
D9  value Green  Io_A: 20mA  [LED_LTST-C190_G]  (hidden comment: LTST-C190KGKT)
D10  value Green  Io_A: 20mA  [LED_LTST-C190_G]  (hidden comment: LTST-C190KGKT)
Q1  value 60V  [SOT-23]  (hidden comment: 2N7002-7-F)
Q2  BSS84-7-F  VdsMax_V: -50V  [SOT-23]
Q3  value 60V  [SOT-23]  (hidden comment: 2N7002-7-F)
Q4  value 60V  [SOT-23]  (hidden comment: 2N7002-7-F)
Q5  value 60V  [SOT-23]  (hidden comment: 2N7002-7-F)
Q6  value 60V  [SOT-23]  (hidden comment: 2N7002-7-F)
Q7  value 60V  [SOT-23]  (hidden comment: 2N7002-7-F)
Q8  value 60V  [SOT-23]  (hidden comment: 2N7002-7-F)
Q9  value 60V  [SOT-23]  (hidden comment: 2N7002-7-F)
R87  ValueDisplayed: 100k  [0402]  (hidden comment: CRCW0402100KJNED)
R88  ValueDisplayed: 100k  [0402]  (hidden comment: CRCW0402100KJNED)
R89  ValueDisplayed: 100k  [0402]  (hidden comment: CRCW0402100KJNED)
R90  ValueDisplayed: 10k  [0402]  (hidden comment: CRCW040210K0JNED)
R91  ValueDisplayed: 10k  [0402]  (hidden comment: CRCW040210K0JNED)
R92  ValueDisplayed: 10k  [0402]  (hidden comment: CRCW040210K0JNED)
R93  ValueDisplayed: 0  [0402]  (hidden comment: CRCW04020000Z0ED)
R94  ValueDisplayed: 100k  [0402]  (hidden comment: CRCW0402100KJNED)
R95  ValueDisplayed: 10k  [0402]  (hidden comment: CRCW040210K0JNED)
R96  ValueDisplayed: 10k  [0402]  (hidden comment: CRCW040210K0JNED)
R97  ValueDisplayed: 0  [0402]  (hidden comment: CRCW04020000Z0ED)
R98  ValueDisplayed: 0  [0402]  (hidden comment: CRCW04020000Z0ED)
R99  ValueDisplayed: 100k  [0402]  (hidden comment: CRCW0402100KJNED)
R100  ValueDisplayed: 10k  [0402]  (hidden comment: CRCW040210K0JNED)
R101  ValueDisplayed: 0  [0402]  (hidden comment: CRCW04020000Z0ED)
R102  ValueDisplayed: 1.0M  [0402]  (hidden comment: CRCW04021M00JNED)
R103  ValueDisplayed: 1.0M  [0402]  (hidden comment: CRCW04021M00JNED)
R104  ValueDisplayed: 1.0M  [0402]  (hidden comment: CRCW04021M00JNED)
R105  ValueDisplayed: 1.0M  [0402]  (hidden comment: CRCW04021M00JNED)
R106  ValueDisplayed: 1.0M  [0402]  (hidden comment: CRCW04021M00JNED)
R107  ValueDisplayed: 1.0M  [0402]  (hidden comment: CRCW04021M00JNED)
R108  ValueDisplayed: 1.0M  [0402]  (hidden comment: CRCW04021M00JNED)
R109  ValueDisplayed: 1.0M  [0402]  (hidden comment: CRCW04021M00JNED)
R110  ValueDisplayed: 1.0M  [0402]  (hidden comment: CRCW04021M00JNED)
R111  ValueDisplayed: 1.0M  [0402]  (hidden comment: CRCW04021M00JNED)
R112  ValueDisplayed: 1.0M  [0402]  (hidden comment: CRCW04021M00JNED)
R113  ValueDisplayed: 1.0M  [0402]  (hidden comment: CRCW04021M00JNED)
R114  ValueDisplayed: 1.0M  [0402]  (hidden comment: CRCW04021M00JNED)
R115  ValueDisplayed: 1.0M  [0402]  (hidden comment: CRCW04021M00JNED)
R116  ValueDisplayed: 1.0M  [0402]  (hidden comment: CRCW04021M00JNED)
R117  ValueDisplayed: 240  [0402]  (hidden comment: CRCW0402240RJNED)
R118  ValueDisplayed: 360  [0402]  (hidden comment: ERJ-2GEJ361X)
R119  ValueDisplayed: 150  [0402]  (hidden comment: CRCW0402150RJNED)
R120  ValueDisplayed: 150  [0402]  (hidden comment: CRCW0402150RJNED)
R121  ValueDisplayed: 160  [0402]  (hidden comment: CRCW0402160RJNED)
R122  ValueDisplayed: 150  [0402]  (hidden comment: CRCW0402150RJNED)
R123  ValueDisplayed: 0  [0402]  (hidden comment: RC0402JR-070RL)
R124  ValueDisplayed: 0  [0402]  (hidden comment: RC0402JR-070RL)
R125  ValueDisplayed: 0  [0402]  (hidden comment: RC0402JR-070RL)
R126  ValueDisplayed: 0  [0402]  (hidden comment: RC0402JR-070RL)
R127  ValueDisplayed: 0  [0402]  (hidden comment: RC0402JR-070RL)
R128  ValueDisplayed: 0  [0402]  (hidden comment: RC0402JR-070RL)
R129  ValueDisplayed: 150  [0402]  (hidden comment: CRCW0402150RJNED)
R130  ValueDisplayed: 150  [0402]  (hidden comment: CRCW0402150RJNED)
R131  ValueDisplayed: 150  [0402]  (hidden comment: CRCW0402150RJNED)
R132  ValueDisplayed: 0  [0402]  (hidden comment: RC0402JR-070RL)
R133  ValueDisplayed: 0  [0402]  (hidden comment: RC0402JR-070RL)
R134  ValueDisplayed: 0  [0402]  (hidden comment: RC0402JR-070RL)
R135  ValueDisplayed: 0  [1206]  (hidden comment: CRCW12060000Z0EA)
R136  ValueDisplayed: 0  [1206]  (hidden comment: CRCW12060000Z0EA)

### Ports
1V8_LDO_PG (in), DDR_End_PG (in), DDR_Strt_PG (in), DDR_TT_PG (in), EN_SEQ_1or2A-Rail (out), EN_SEQ_8A-Rail (out), EN_SEQ_12A-Rail (out), EN_SEQ_DC1A (out), EN_SEQ_DC1B (out), EN_SEQ_DC2A (out), EN_SEQ_DC2B (out), EN_SEQ_DC3A (out), EN_SEQ_DC3B (out), EN_SEQ_DDR_TT (out), EN_SEQ_LDOA (out), EN_SEQ_LDOB (out), EN_SEQ_LS1 (out), EN_SEQ_LS2 (out), EN_SEQ_LS3 (out), HiCurrent_PG (in), MAIN_PWR_GOOD, MidCurrent_PG (in), PMIC1_DC1_PG (in)

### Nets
GND: C99.2 C100.2 C101.2 C102.2 C103.2 C104.2 C105.2 C106.2 C107.2 C108.2 C109.2 C110.2 C111.2 C112.2 C113.2 Q1.2(S) Q3.2(S) Q4.2(S) Q5.2(S) Q6.2(S) Q7.2(S) Q8.2(S) Q9.2(S) R102.1 R103.1 R104.1 R105.1 R106.1 R107.1 R108.1 R109.1 R110.1 R111.1 R112.1 R113.1 R114.1 R115.1 R116.1 R118.1
VIO: R87.1 R88.1 R89.1 R90.1 R91.1 R92.1 R93.2 R94.1 R95.1 R96.1 R97.2 R98.2 R99.1 R100.1 R101.2
VLDO2A_3V3: R136.2
VLED: Q2.2(S) R117.2 R119.2 R120.2 R121.2 R122.2 R129.2 R130.2 R131.2 R135.1 R136.1
VSYS: R135.2
BUCK_1or2A_EN: C103.1 R91.2 R106.2 ; port EN_SEQ_1or2A-Rail
BUCK_8A_EN: C104.1 R92.2 R107.2 ; port EN_SEQ_8A-Rail
BUCK_12A_EN: C105.1 R93.1 R108.2 ; port EN_SEQ_12A-Rail
DCDC1_EN_A: C112.1 R100.2 R115.2 ; port EN_SEQ_DC1A
DCDC1_EN_B: C108.1 R96.2 R111.2 ; port EN_SEQ_DC1B
DCDC2_EN_A: C111.1 R99.2 R114.2 ; port EN_SEQ_DC2A
DCDC2_EN_B: C107.1 R95.2 R110.2 ; port EN_SEQ_DC2B
DCDC3_EN_A: C110.1 R98.1 R113.2 ; port EN_SEQ_DC3A
DCDC3_EN_B: C106.1 R94.2 R109.2 ; port EN_SEQ_DC3B
DDR_Strt_PG: R126.1 ; port DDR_Strt_PG
DDR_TT_PG: R127.1 ; port DDR_TT_PG
EN_DDR_TERM: C102.1 R90.2 R105.2 ; port EN_SEQ_DDR_TT
EN_SEQ_LDOA: C113.1 R101.1 R116.2 ; port EN_SEQ_LDOA
EN_SEQ_LDOB: C109.1 R97.1 R112.2 ; port EN_SEQ_LDOB
EN_SEQ_LS1: C101.1 R89.2 R104.2 ; port EN_SEQ_LS1
EN_SEQ_LS2: C100.1 R88.2 R103.2 ; port EN_SEQ_LS2
EN_SEQ_LS3: C99.1 R87.2 R102.2 ; port EN_SEQ_LS3
HiCurrent_PG: R132.1 ; port HiCurrent_PG
LOW_BATz_A: R125.1 ; port PMIC1_DC1_PG
LOW_BATz_B: R128.1 ; port DDR_End_PG
PWRFAILz_A: R123.1 R124.1 ; port MAIN_PWR_GOOD
PWRFAILz_B: R134.1 ; port 1V8_LDO_PG
NetD2_1: D2.1(K) Q1.3(D)
NetD2_2: D2.2(A) R117.1
NetD3_1: D3.1(A) Q2.3(D)
NetD3_2: D3.2(K) R118.2
NetD4_1: D4.1(A) R119.1
NetD4_2: D4.2(K) Q3.3(D)
NetD5_1: D5.1(A) R120.1
NetD5_2: D5.2(K) Q4.3(D)
NetD6_1: D6.1(A) R121.1
NetD6_2: D6.2(K) Q5.3(D)
NetD7_1: D7.1(A) R122.1
NetD7_2: D7.2(K) Q6.3(D)
NetD8_1: D8.1(A) R129.1
NetD8_2: D8.2(K) Q7.3(D)
NetD9_1: D9.1(A) R130.1
NetD9_2: D9.2(K) Q8.3(D)
NetD10_1: D10.1(A) R131.1
NetD10_2: D10.2(K) Q9.3(D)
NetQ1_1: Q1.1(G) R123.2
NetQ2_1: Q2.1(G) R124.2
NetQ3_1: Q3.1(G) R125.2
NetQ4_1: Q4.1(G) R126.2
NetQ5_1: Q5.1(G) R127.2
NetQ6_1: Q6.1(G) R128.2
NetQ7_1: Q7.1(G) R132.2
NetQ8_1: Q8.1(G) R133.2
NetQ9_1: Q9.1(G) R134.2

Not connected (* = marked no-connect by the designer): R133 1

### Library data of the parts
C99-C102 = CMP-0006406-2: CAP, CERM, 910 pF, 25 V, +/- 5%, C0G/NP0, 0402; Manufacturer: MuRata; TaMin_C: -55°C; Polarized: N; SizeAreaWB_mm2: 3; Value1: Unknown; U/M: EA; Value: 910pF; TaMax_C: 125°C; SizeZ_mm: 0.6; SizeX_mm: 1; SizeY_mm: 0.5; AEC Category: Q200
C103 C106 C107 = CMP-0006393-2: CAP, CERM, 510 pF, 25 V, +/- 5%, C0G/NP0, 0402; Manufacturer: MuRata; TaMin_C: -55°C; Polarized: N; SizeAreaWB_mm2: 3; Value1: Unknown; U/M: EA; Value: 510pF; TaMax_C: 125°C; SizeZ_mm: 0.6; SizeX_mm: 1; SizeY_mm: 0.5; AEC Category: Q200
C104 C108 C111 C112 = CMP-0006410-2: CAP, CERM, 100 pF, 50 V, +/- 5%, C0G/NP0, 0402; Manufacturer: MuRata; TaMin_C: -55°C; Polarized: N; SizeAreaWB_mm2: 3; Value1: Unknown; U/M: EA; Value: 100pF; TaMax_C: 125°C; SizeZ_mm: 0.6; SizeX_mm: 1; SizeY_mm: 0.5; AEC Category: Q200
C105 C109 C110 C113 = CMP-0064916-2: CAP, CERM, 10 pF, 50 V,+/- 1%, C0G/NP0, 0402; Manufacturer: MuRata; TaMin_C: -55°C; Polarized: N; SizeAreaWB_mm2: 3; Value1: Unknown; U/M: EA; Value: 10pF; TaMax_C: 125°C; SizeZ_mm: 0.6; SizeX_mm: 1; SizeY_mm: 0.5; AEC Category: Q200
D2 = CMP-0002884-1: LED, Cool White, SMD; Manufacturer: Panasonic; Value1: W; U/M: EA
D3 = CMP-0067668-1: LED, Red, SMD; Manufacturer: Vishay-Semiconductor; Power_TotalModule: 200mW; SizeAreaWB_mm2: 17.1; Vr_V: 5V; Tjmax_C: 125°C; Value1: 0.2W; U/M: EA; Angle: 120.0; SizeZ_mm: 1.85; SizeX_mm: 3.5; SizeY_mm: 2.8; Ir_A: 10µA; Vf_V: 2.2V; SizeArea_mm2: 9.8; Type: AlInGaP
D4 D7-D10 = LTST-C190KGKT: LED, Green, SMD; Manufacturer: Lite-On; Type: AlInGaP; Vf_V: 2; Value2: 2V; Tjmax_C: 85; Value1: W; U/M: EA
D5 = LTST-C190KFKT: LED, Orange, SMD; Manufacturer: Lite-On; Type: AlInGaP; Vf_V: 2; Value2: 2V; Power_TotalModule: 0.075; Value1: 0.075W; U/M: EA
D6 = CMP-0002862-1: LED, Yellow , SMD; Manufacturer: Lite-On; SizeAreaWB_mm2: 6.75; Value1: W; U/M: EA; SizeZ_mm: 1.2; SizeX_mm: 2; SizeY_mm: 1.25; Vf_V: 2V; SizeArea_mm2: 2.5; Type: AlInGaP
Q1 Q3-Q9 = 2N7002-7-F: MOSFET, N-CH, 60V, 0.17A, SOT-23; Manufacturer: Diodes Inc.; Alternate Manufacturer: None; U/M: EA; ChType: N; VdsMax_V: 60; Value1: 7.5 ohm; Rdson45_Ohm: 7.5; Value2: 223 nC; QgTyp_nC: 223; Vgs_V: 20; IdsMax_A: 0.17
Q2 = CMP-0000011-2: MOSFET, P-CH, -50 V, -0.13 A, SOT-23; Alternate Manufacturer: None; Manufacturer: Diodes Inc.; SizeZ_mm: 1.1; ChType: P; SizeX_mm: 2.5; SizeY_mm: 3; Vgs_V: -20V; AEC Qualified: N; Value: -50V; SizeArea_mm2: 7.5; AEC Category: Q101; IdsMax_A: -1.3dA; SizeAreaWB_mm2: 14; U/M: EA
R87-R89 R94 R99 = CMP-0026823-2: as R82 on sheet TIDA01480_pg4_DscrtRls
R90-R92 R95 R96 R100 = CMP-0026825-4: as R60 on sheet TIDA01480_pg4_DscrtRls
R93 R97 R98 R101 = CMP-0026822-2: as R81 on sheet TIDA01480_pg4_DscrtRls
R102-R116 = CMP-0026859-1: as R157 on sheet TIDA01480_pg4_DscrtRls
R117 = CMP-0026882-2: RES, 240, 5%, 0.063 W, 0402; Manufacturer: Vishay-Dale; Power_W: 63mW; TempCo: 200 ppm/C; Value_Code: 240R; U/M: EA; Value: 240; EIA_Code: E24; SizeX_mm: 1; SizeY_mm: 0.5; SizeZ_mm: 0.6; Value2: 0.063W; VDC_V: 50V; AEC Category: Q200
R118 = CMP-0078194-1: RES, 360, 5%, 0.1 W, AEC-Q200 Grade 0, 0402; Manufacturer: Panasonic; Value_Code: 360R; SizeArea_mm2: 0.5; AEC Qualified: Y; AEC Category: Q200; Value: 360; SizeZ_mm: 0.6; EIA_Code: E24; TempCo: 200 ppm/C; AEC Grade: 0; Power_W: 100mW; VDC_V: 50V; Value2: 0.1W; U/M: EA; SizeX_mm: 1
R119 R120 R122 R129-R131 = CMP-0026841-2: RES, 150, 5%, 0.063 W, 0402; Manufacturer: Vishay-Dale; Power_W: 63mW; TempCo: 200 ppm/C; Value_Code: 150R; U/M: EA; Value: 150; EIA_Code: E24; SizeX_mm: 1; SizeY_mm: 0.5; SizeZ_mm: 0.6; Value2: 0.063W; VDC_V: 50V; AEC Category: Q200
R121 = CMP-0026845-2: RES, 160, 5%, 0.063 W, 0402; Manufacturer: Vishay-Dale; Power_W: 63mW; TempCo: 200 ppm/C; Value_Code: 160R; U/M: EA; Value: 160; EIA_Code: E24; SizeX_mm: 1; SizeY_mm: 0.5; SizeZ_mm: 0.6; Value2: 0.063W; VDC_V: 50V; AEC Category: Q200
R123-R128 R132-R134 = CMP-0027004-2: RES, 0, 5%, 0.063 W, 0402; Manufacturer: Yageo America; Power_W: 63mW; TempCo: 200 ppm/C; Value_Code: 0000; U/M: EA; Value: 0; EIA_Code: E24; SizeX_mm: 1; SizeY_mm: 0.5; SizeZ_mm: 0.6; Value2: 0.063W; VDC_V: 50V; AEC Category: Q200
R135 = CMP-0018573-2: as R62 on sheet TIDA01480_pg4_DscrtRls
R136 = CMP-0018573-2: RES, 0, 5%, 0.25 W, 1206; Manufacturer: Vishay-Dale; Power_W: 250mW; TempCo: 200 ppm/C; Value_Code: 0000; U/M: EA; Value: 0; EIA_Code: E24; SizeX_mm: 3.2; SizeY_mm: 1.6; SizeZ_mm: 1.35; Value2: 0.25W; SizeArea_mm2: 5.12; CompType: Resistor; VDC_V: 200V; AEC Category: Q200

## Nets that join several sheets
AGND: TIDA01480_pg3_Main (18 pins), TIDA01480_pg4_DscrtRls (9 pins)
GND: TIDA01480_pg3_Main (74 pins), TIDA01480_pg5_OutPwrRails (47 pins), TIDA01480_pg4_DscrtRls (70 pins), TIDA01480_pg6_MiscSignals (39 pins)
VCC_1or2A: TIDA01480_pg5_OutPwrRails (6 pins), TIDA01480_pg4_DscrtRls (9 pins)
VCC_8A: TIDA01480_pg5_OutPwrRails (J6.4 R138.2 R150.1 R150.2), TIDA01480_pg4_DscrtRls (7 pins)
VCC_12A: TIDA01480_pg5_OutPwrRails (J6.1 R137.1 R145.1 R145.2), TIDA01480_pg4_DscrtRls (13 pins)
VDCDC1_A: TIDA01480_pg3_Main (16 pins), TIDA01480_pg5_OutPwrRails (6 pins)
VDCDC1_B: TIDA01480_pg3_Main (9 pins), TIDA01480_pg5_OutPwrRails (6 pins)
VDCDC2_A: TIDA01480_pg3_Main (7 pins), TIDA01480_pg5_OutPwrRails (5 pins)
VDCDC2_B: TIDA01480_pg3_Main (13 pins), TIDA01480_pg5_OutPwrRails (5 pins), TIDA01480_pg4_DscrtRls (R67.2 R69.2)
VDCDC3_A: TIDA01480_pg3_Main (7 pins), TIDA01480_pg5_OutPwrRails (5 pins), TIDA01480_pg4_DscrtRls (R68.2)
VDCDC3_B: TIDA01480_pg3_Main (7 pins), TIDA01480_pg5_OutPwrRails (5 pins)
VDDR: TIDA01480_pg3_Main (R34.2), TIDA01480_pg5_OutPwrRails (J7.3), TIDA01480_pg4_DscrtRls (6 pins)
VIO: TIDA01480_pg3_Main (12 pins), TIDA01480_pg4_DscrtRls (9 pins), TIDA01480_pg6_MiscSignals (15 pins)
VLDO1A_1V8: TIDA01480_pg3_Main (C23.1 R40.2 U1.20), TIDA01480_pg5_OutPwrRails (J7.53)
VLDO2A_3V3: TIDA01480_pg3_Main (C24.1 U1.18), TIDA01480_pg5_OutPwrRails (J7.55), TIDA01480_pg4_DscrtRls (C92.1 R70.2 R80.1 U9.10), TIDA01480_pg6_MiscSignals (R136.2)
VSYS: TIDA01480_pg3_Main (31 pins), TIDA01480_pg4_DscrtRls (24 pins), TIDA01480_pg6_MiscSignals (R135.2)
BUCK_1or2A_EN: TIDA01480_pg5_OutPwrRails (J7.20), TIDA01480_pg4_DscrtRls (U8.5), TIDA01480_pg6_MiscSignals (C103.1 R91.2 R106.2)
BUCK_8A_EN: TIDA01480_pg5_OutPwrRails (J7.118), TIDA01480_pg4_DscrtRls (U7.15), TIDA01480_pg6_MiscSignals (C104.1 R92.2 R107.2)
BUCK_12A_EN: TIDA01480_pg5_OutPwrRails (J7.117), TIDA01480_pg4_DscrtRls (U5.15), TIDA01480_pg6_MiscSignals (C105.1 R93.1 R108.2)
DCDC1_EN_A: TIDA01480_pg3_Main (U1.25), TIDA01480_pg5_OutPwrRails (J7.52), TIDA01480_pg6_MiscSignals (C112.1 R100.2 R115.2)
DCDC1_EN_B: TIDA01480_pg3_Main (U3.25), TIDA01480_pg5_OutPwrRails (J7.48), TIDA01480_pg6_MiscSignals (C108.1 R96.2 R111.2)
DCDC2_EN_A: TIDA01480_pg3_Main (U1.24), TIDA01480_pg5_OutPwrRails (J7.54), TIDA01480_pg6_MiscSignals (C111.1 R99.2 R114.2)
DCDC2_EN_B: TIDA01480_pg3_Main (U3.24), TIDA01480_pg5_OutPwrRails (J7.46), TIDA01480_pg6_MiscSignals (C107.1 R95.2 R110.2)
DCDC3_EN_A: TIDA01480_pg3_Main (U1.23), TIDA01480_pg5_OutPwrRails (J7.56), TIDA01480_pg6_MiscSignals (C110.1 R98.1 R113.2)
DCDC3_EN_B: TIDA01480_pg3_Main (U3.23), TIDA01480_pg5_OutPwrRails (J7.44), TIDA01480_pg6_MiscSignals (C106.1 R94.2 R109.2)
DDR_Strt_PG: TIDA01480_pg5_OutPwrRails (J7.24), TIDA01480_pg4_DscrtRls (R84.2 U8.6), TIDA01480_pg6_MiscSignals (R126.1)
DDR_TT_PG: TIDA01480_pg5_OutPwrRails (J7.16), TIDA01480_pg4_DscrtRls (R82.2 U9.9), TIDA01480_pg6_MiscSignals (R127.1)
EN_DDR_TERM: TIDA01480_pg5_OutPwrRails (J7.18), TIDA01480_pg4_DscrtRls (R85.2), TIDA01480_pg6_MiscSignals (C102.1 R90.2 R105.2)
EN_PRE_BUCK: TIDA01480_pg5_OutPwrRails (J7.114), TIDA01480_pg4_DscrtRls (J3.4 R155.2 R157.2)
EN_SEQ_LDOA: TIDA01480_pg3_Main (U1.22), TIDA01480_pg5_OutPwrRails (J7.58), TIDA01480_pg6_MiscSignals (C113.1 R101.1 R116.2)
EN_SEQ_LDOB: TIDA01480_pg3_Main (U3.22), TIDA01480_pg5_OutPwrRails (J7.42), TIDA01480_pg6_MiscSignals (C109.1 R97.1 R112.2)
EN_SEQ_LS1: TIDA01480_pg3_Main (U2.D2), TIDA01480_pg5_OutPwrRails (J7.92), TIDA01480_pg6_MiscSignals (C101.1 R89.2 R104.2)
EN_SEQ_LS2: TIDA01480_pg3_Main (U4.D2), TIDA01480_pg5_OutPwrRails (J7.22), TIDA01480_pg6_MiscSignals (C100.1 R88.2 R103.2)
EN_SEQ_LS3: TIDA01480_pg5_OutPwrRails (J7.94), TIDA01480_pg4_DscrtRls (U6.D2), TIDA01480_pg6_MiscSignals (C99.1 R87.2 R102.2)
HiCurrent_PG: TIDA01480_pg5_OutPwrRails (J7.115), TIDA01480_pg4_DscrtRls (R60.2 U5.16), TIDA01480_pg6_MiscSignals (R132.1)
HV_AIC_PG: TIDA01480_pg5_OutPwrRails (J7.112), TIDA01480_pg4_DscrtRls (J4.4 R156.2)
I2C_CLK_A: TIDA01480_pg3_Main (R3.1 U1.30), TIDA01480_pg5_OutPwrRails (J7.70)
I2C_CLK_B: TIDA01480_pg3_Main (R31.1 U3.30), TIDA01480_pg5_OutPwrRails (J7.86)
I2C_DAT_A: TIDA01480_pg3_Main (R4.1 U1.29), TIDA01480_pg5_OutPwrRails (J7.68)
I2C_DAT_B: TIDA01480_pg3_Main (R32.1 U3.29), TIDA01480_pg5_OutPwrRails (J7.84)
INTERRUPTz_A: TIDA01480_pg3_Main (R14.1 U1.28), TIDA01480_pg5_OutPwrRails (J7.66)
INTERRUPTz_B: TIDA01480_pg3_Main (R47.1 U3.28), TIDA01480_pg5_OutPwrRails (J7.82)
LDO1B__or__VPS_MTRAVTT: TIDA01480_pg3_Main (C48.1 U3.20), TIDA01480_pg5_OutPwrRails (J7.49)
LDO2B: TIDA01480_pg3_Main (C49.1 U3.18), TIDA01480_pg5_OutPwrRails (J7.47)
LOW_BATz_A: TIDA01480_pg3_Main (R12.1 U1.21), TIDA01480_pg5_OutPwrRails (J7.62), TIDA01480_pg6_MiscSignals (R125.1)
LOW_BATz_B: TIDA01480_pg3_Main (R45.1 U3.21), TIDA01480_pg5_OutPwrRails (J7.78), TIDA01480_pg6_MiscSignals (R128.1)
MidCurrent_PG: TIDA01480_pg5_OutPwrRails (J7.116), TIDA01480_pg4_DscrtRls (R72.2 U7.16)
PWRFAILz_A: TIDA01480_pg3_Main (R10.2 R11.1 U1.31), TIDA01480_pg5_OutPwrRails (J7.72), TIDA01480_pg6_MiscSignals (R123.1 R124.1)
PWRFAILz_B: TIDA01480_pg3_Main (R43.2 R44.1 U3.31), TIDA01480_pg5_OutPwrRails (J7.88), TIDA01480_pg6_MiscSignals (R134.1)
RESETz_A: TIDA01480_pg3_Main (R13.1 U1.27), TIDA01480_pg5_OutPwrRails (J7.64)
RESETz_B: TIDA01480_pg3_Main (R46.1 U3.27), TIDA01480_pg5_OutPwrRails (J7.80)
VCC_12A_LS3: TIDA01480_pg5_OutPwrRails (J7.103), TIDA01480_pg4_DscrtRls (5 pins)
VCC_PSPLL: TIDA01480_pg3_Main (5 pins), TIDA01480_pg5_OutPwrRails (J7.97)
VDCDC2_B_LS2: TIDA01480_pg3_Main (5 pins), TIDA01480_pg5_OutPwrRails (J7.14)
VREFCA_DDR: TIDA01480_pg5_OutPwrRails (J7.23), TIDA01480_pg4_DscrtRls (C95.1 U9.6)
VRTC_A: TIDA01480_pg3_Main (C25.1 R10.1 U1.16), TIDA01480_pg5_OutPwrRails (J7.28)
VRTC_B: TIDA01480_pg3_Main (C50.1 R43.1 U3.16), TIDA01480_pg5_OutPwrRails (J7.26)
VTT: TIDA01480_pg5_OutPwrRails (J7.19 J7.21), TIDA01480_pg4_DscrtRls (6 pins)

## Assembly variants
001: not fitted C9 C10 C11 C26 C27 C28 C29 C30 C31 C32 C33 C34 C35 C36 C37 C38 C39 C40 C41 C42 C43 C44 C45 C46 C47 C48 C49 C50 C64 C65 C66 C115 D1 FID1 FID2 FID3 J3 J4 J5 L4 L5 L6 R2 R18 R19 R20 R25 R27 R28 R29 R30 R31 R32 R33 R34 R35 R36 R37 R38 R39 R40 R41 R42 R43 R44 R45 R46 R47 R48 R49 R50 R51 R52 R53 R54 R55 R56 R57 R58 R59 R62 R67 R68 R69 R71 R78 R135 R137 R138 R140 R142 R144 R148 R149 R151 R153 R155 R156 R157 S2 U2 U3 U3 U4 U6
002: not fitted C9 C10 C11 C40 C41 C42 C64 C65 C66 C82 C83 C84 C88 C89 C90 C91 C93 D1 FID1 FID2 FID3 J3 J4 J5 L9 R2 R18 R19 R20 R25 R27 R28 R33 R39 R41 R51 R52 R53 R57 R58 R59 R62 R66 R68 R69 R71 R78 R83 R84 R86 R135 R137 R138 R140 R142 R144 R148 R149 R151 R153 R155 R156 R157 S2 U2 U4 U6 U8
003: not fitted C9 C10 C11 C40 C41 C42 C64 C65 C66 C82 C83 C84 C85 C86 C87 C88 C89 C90 C91 C92 C93 C94 C95 C96 C97 C98 D1 FID1 FID2 FID3 J3 J4 J5 L9 R2 R18 R19 R20 R25 R27 R28 R33 R39 R41 R51 R52 R53 R57 R58 R59 R62 R66 R67 R68 R69 R71 R80 R81 R82 R83 R84 R85 R86 R135 R137 R138 R140 R142 R144 R148 R149 R151 R153 R155 R156 R157 S2 U2 U4 U6 U8 U9
004: not fitted C9 C10 C11 C40 C41 C42 C64 C65 C66 C82 C83 C84 C88 C89 C90 C91 C93 D1 FID1 FID2 FID3 J3 J4 J5 L9 R2 R18 R19 R20 R25 R27 R28 R33 R39 R41 R51 R52 R53 R57 R58 R59 R62 R66 R68 R69 R71 R78 R83 R84 R86 R135 R137 R138 R140 R142 R144 R148 R149 R151 R153 R155 R156 R157 S2 U2 U4 U6 U8
005: not fitted D1 FID1 FID2 FID3 J3 J4 J5 R2 R18 R19 R20 R25 R27 R28 R33 R39 R41 R51 R52 R53 R57 R58 R59 R62 R67 R68 R69 R71 R78 R135 R137 R138 R140 R142 R144 R148 R149 R151 R153 R155 R156 R157 S2
006: not fitted C9 C10 C11 C26 C27 C28 C29 C30 C31 C32 C33 C34 C35 C36 C37 C38 C39 C40 C41 C42 C43 C44 C45 C46 C47 C48 C49 C50 C64 C65 C66 C115 D1 FID1 FID2 FID3 J3 J4 J5 L4 L5 L6 R2 R18 R19 R20 R25 R27 R28 R29 R30 R31 R32 R33 R34 R35 R36 R37 R38 R39 R40 R41 R42 R43 R44 R45 R46 R47 R48 R49 R50 R51 R52 R53 R54 R55 R56 R57 R58 R59 R62 R67 R68 R69 R71 R78 R135 R137 R138 R140 R142 R144 R148 R149 R151 R153 R155 R156 R157 S2 U2 U3 U3 U4 U6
